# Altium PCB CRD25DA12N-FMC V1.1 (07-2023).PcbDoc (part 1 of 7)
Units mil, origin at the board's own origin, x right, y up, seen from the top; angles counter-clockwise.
Board outline 8000 x 8000 mil, 6 copper layers (Top Layer, Layer 2, Layer 3, Layer 4, Layer 5, Bottom Layer), stack 91 mil thick; 542 components, 315 nets, 1585 pads, 558 vias.
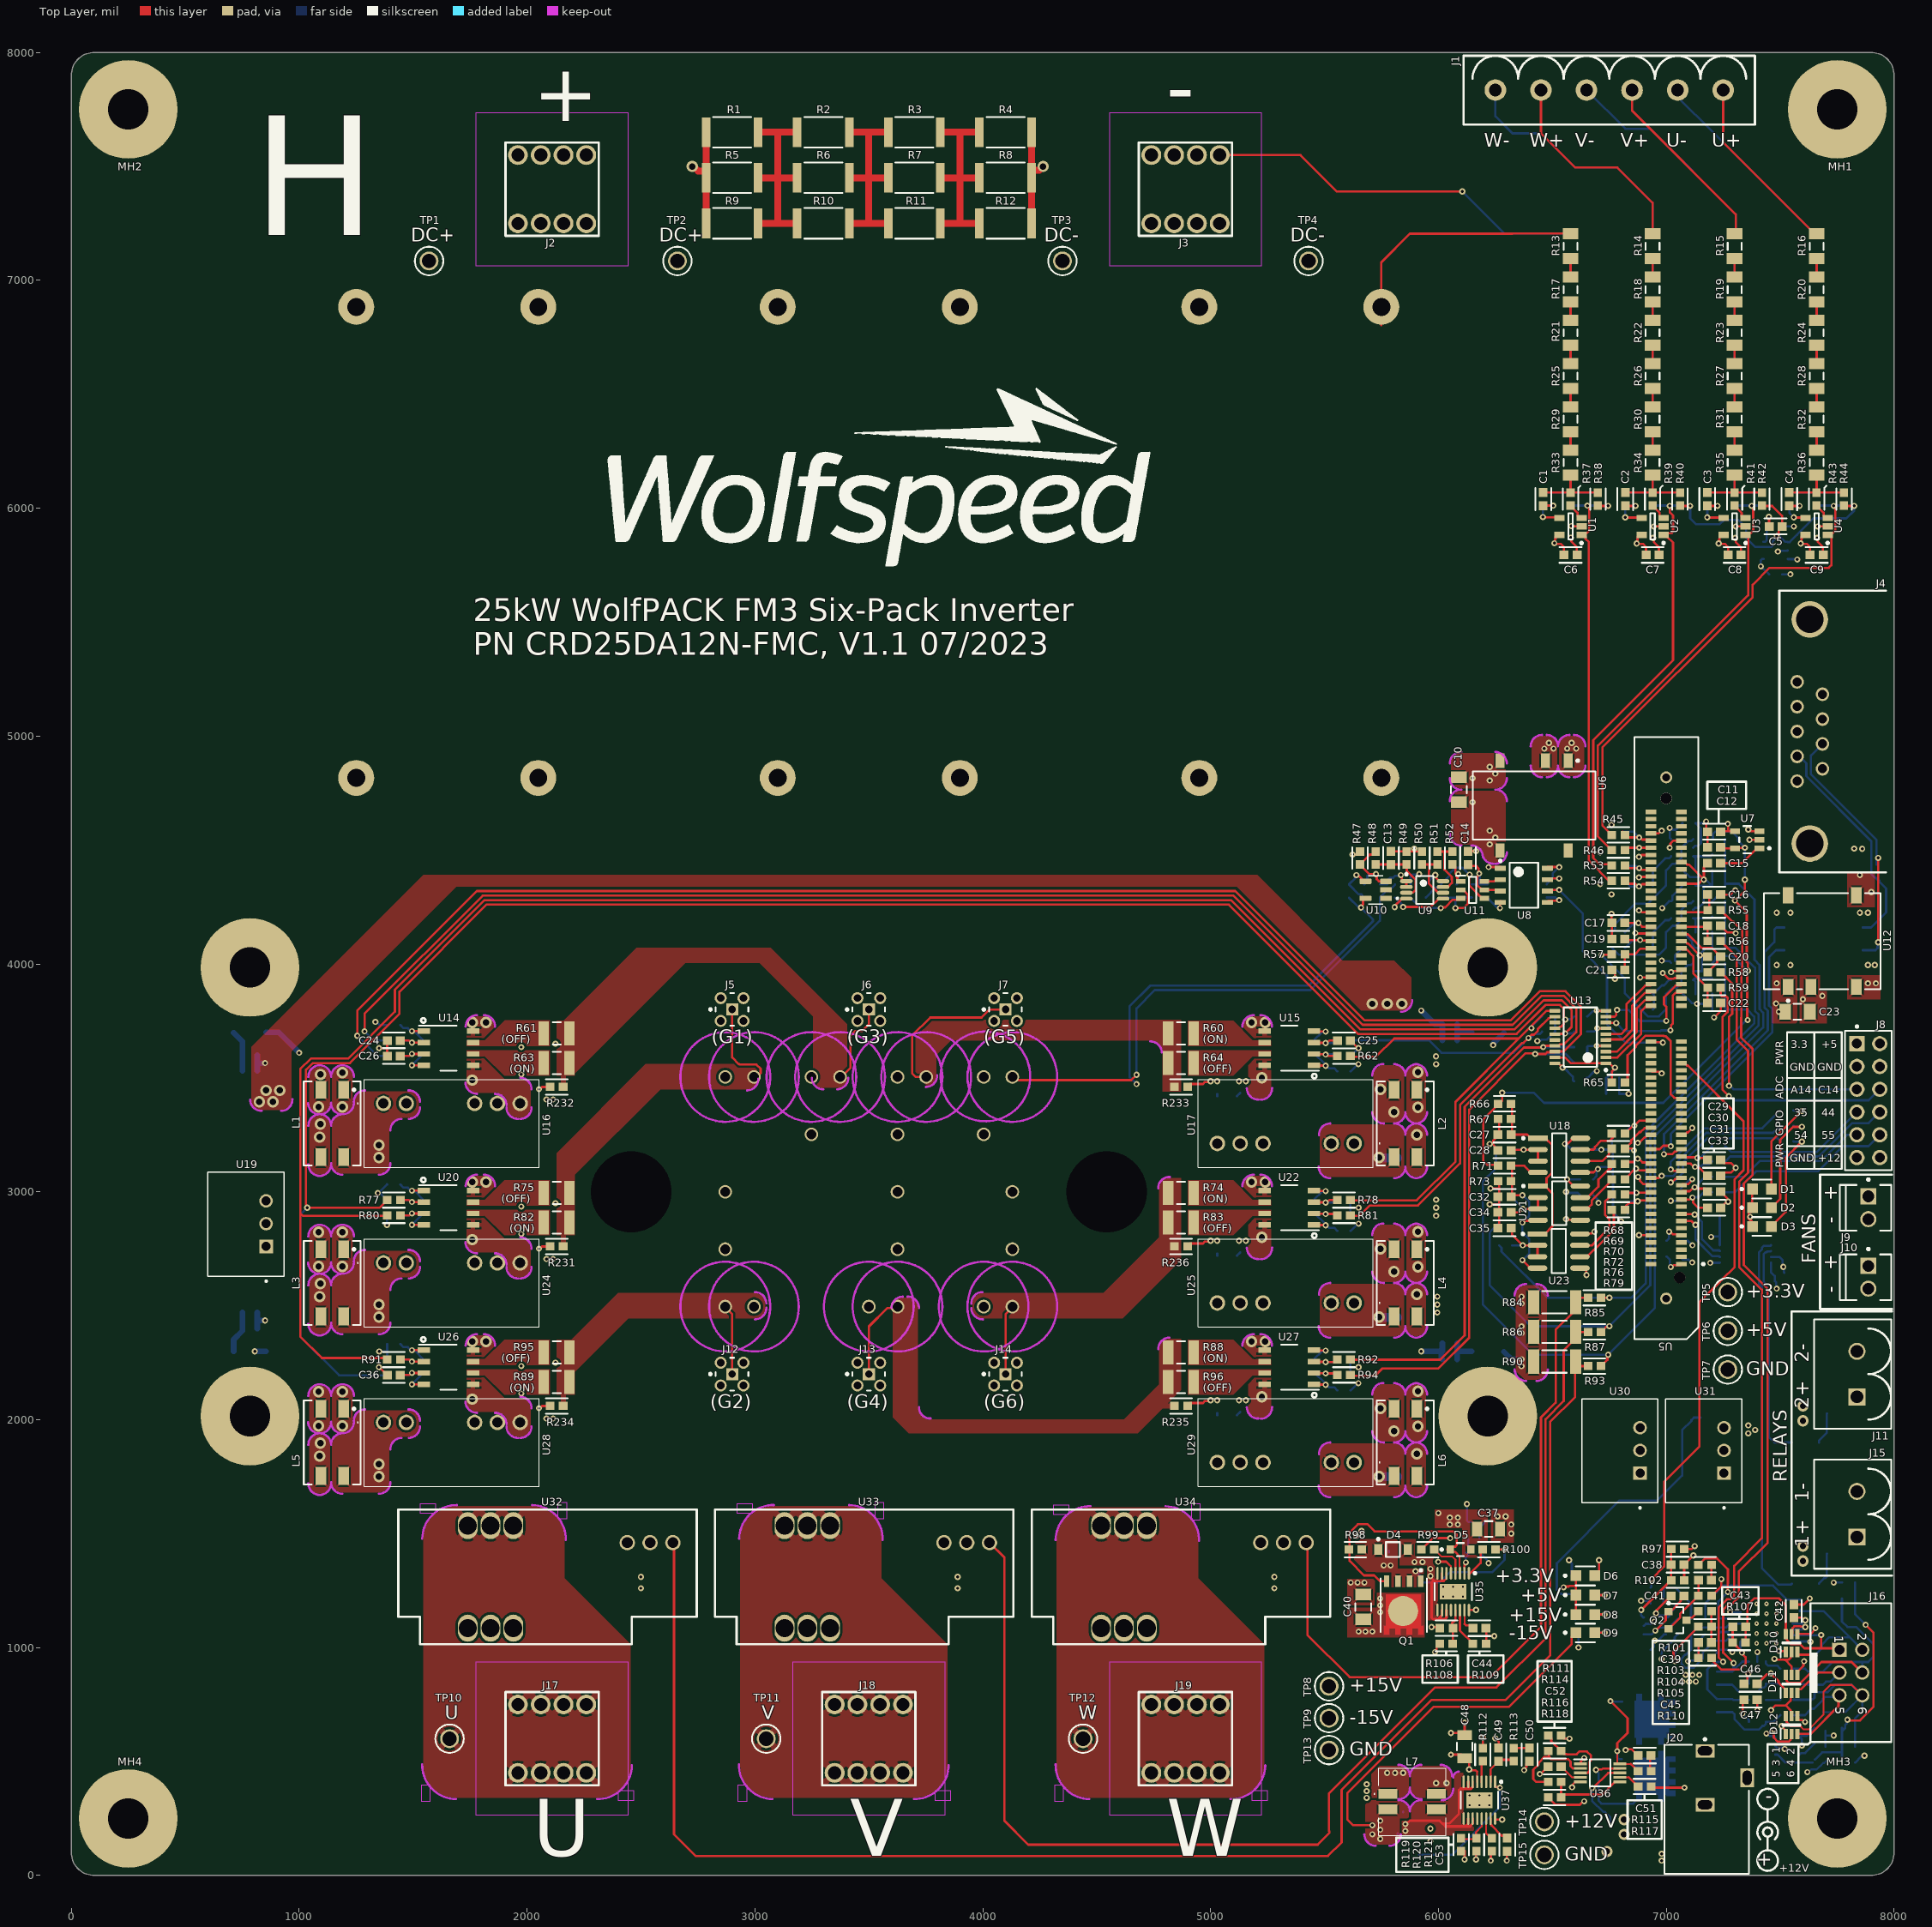
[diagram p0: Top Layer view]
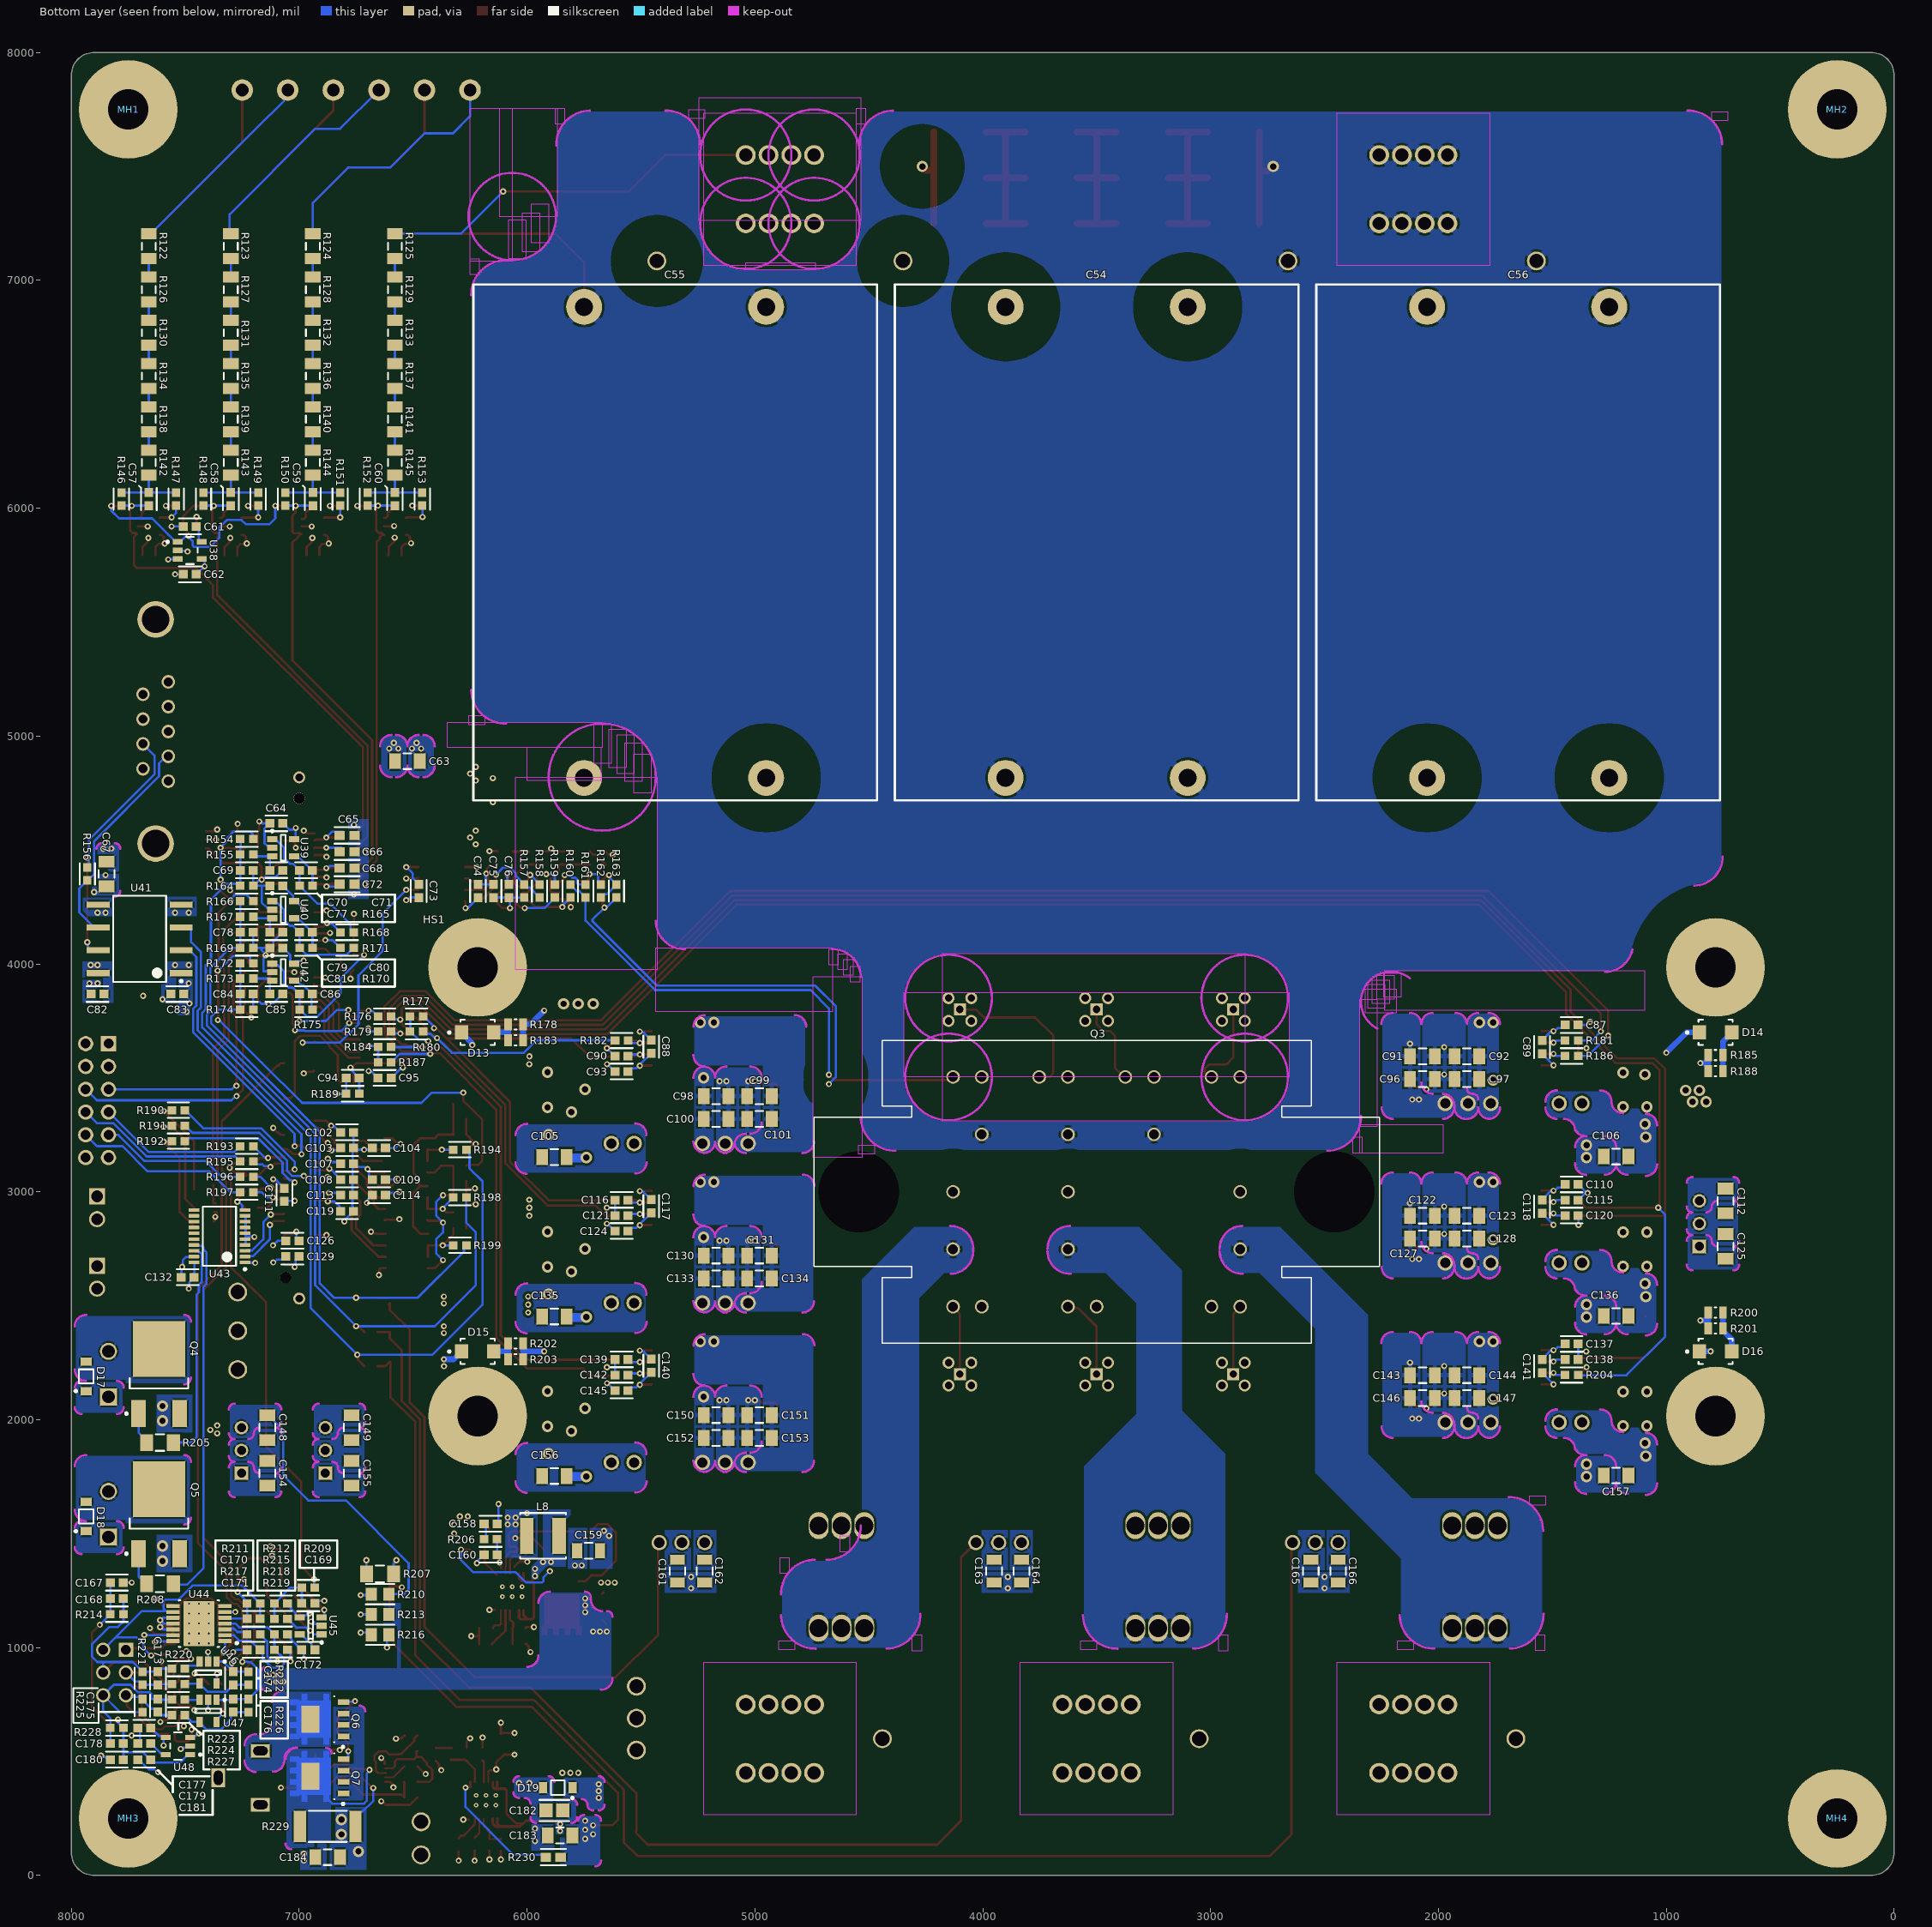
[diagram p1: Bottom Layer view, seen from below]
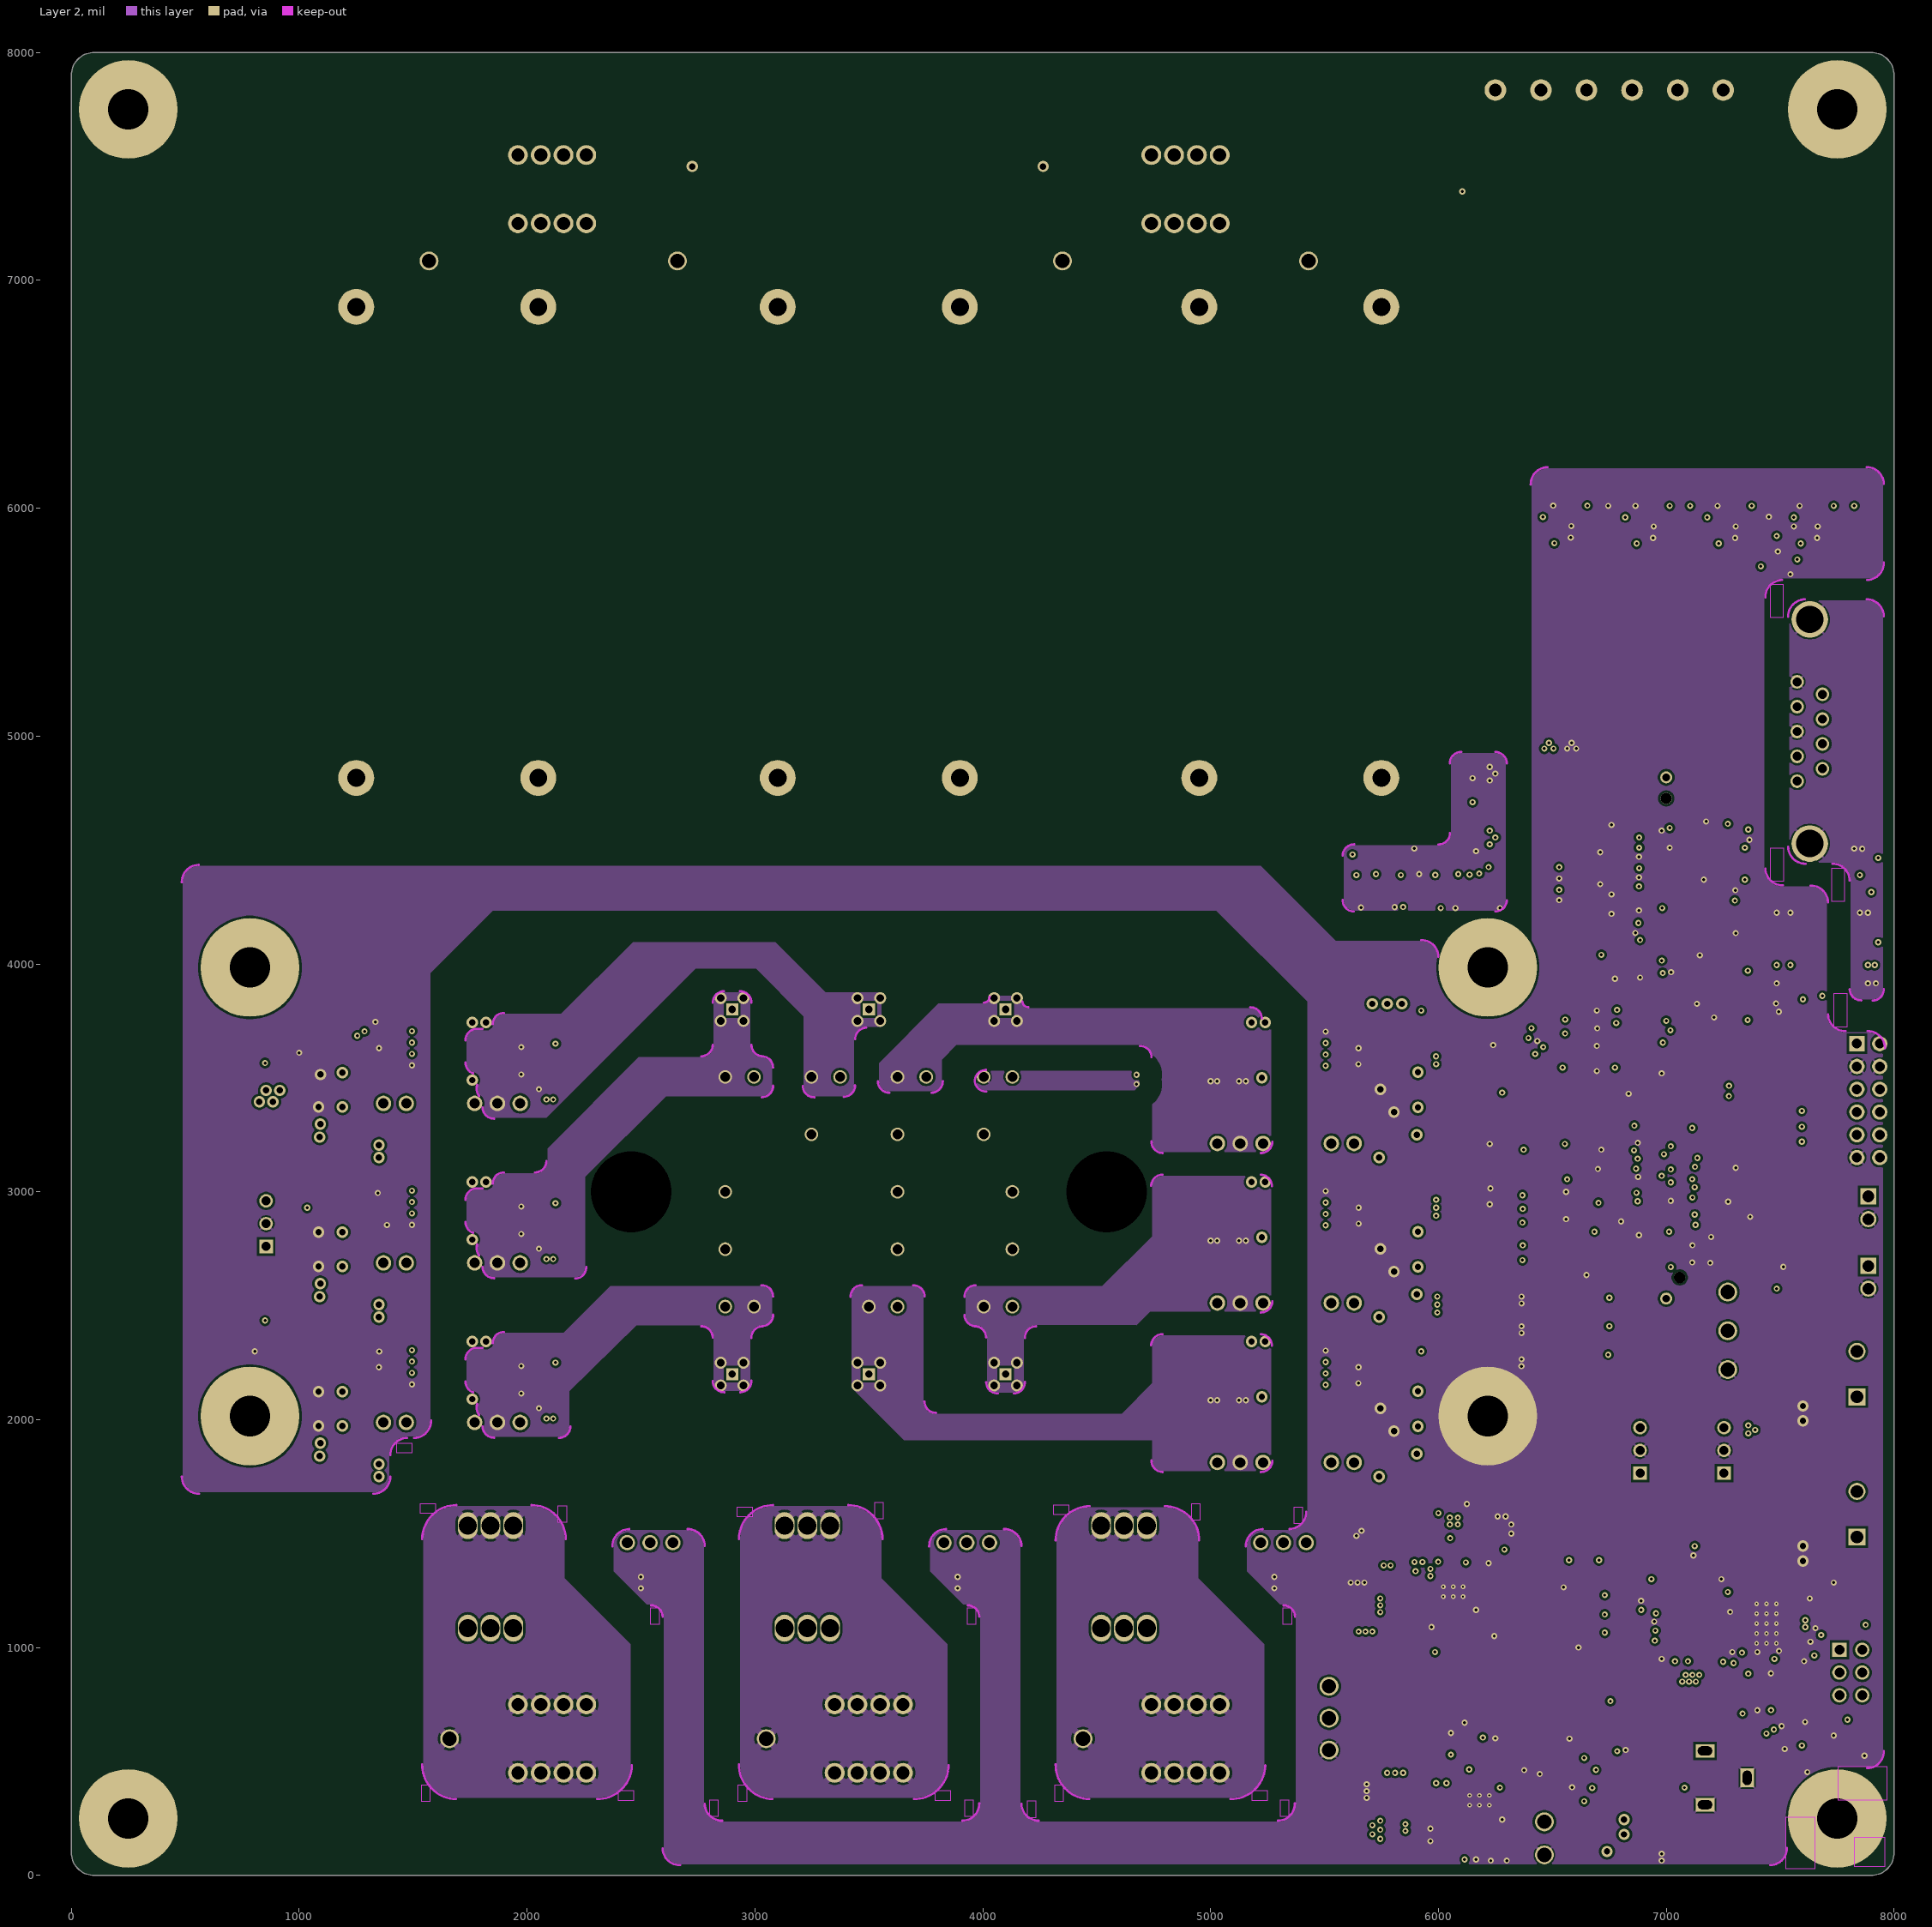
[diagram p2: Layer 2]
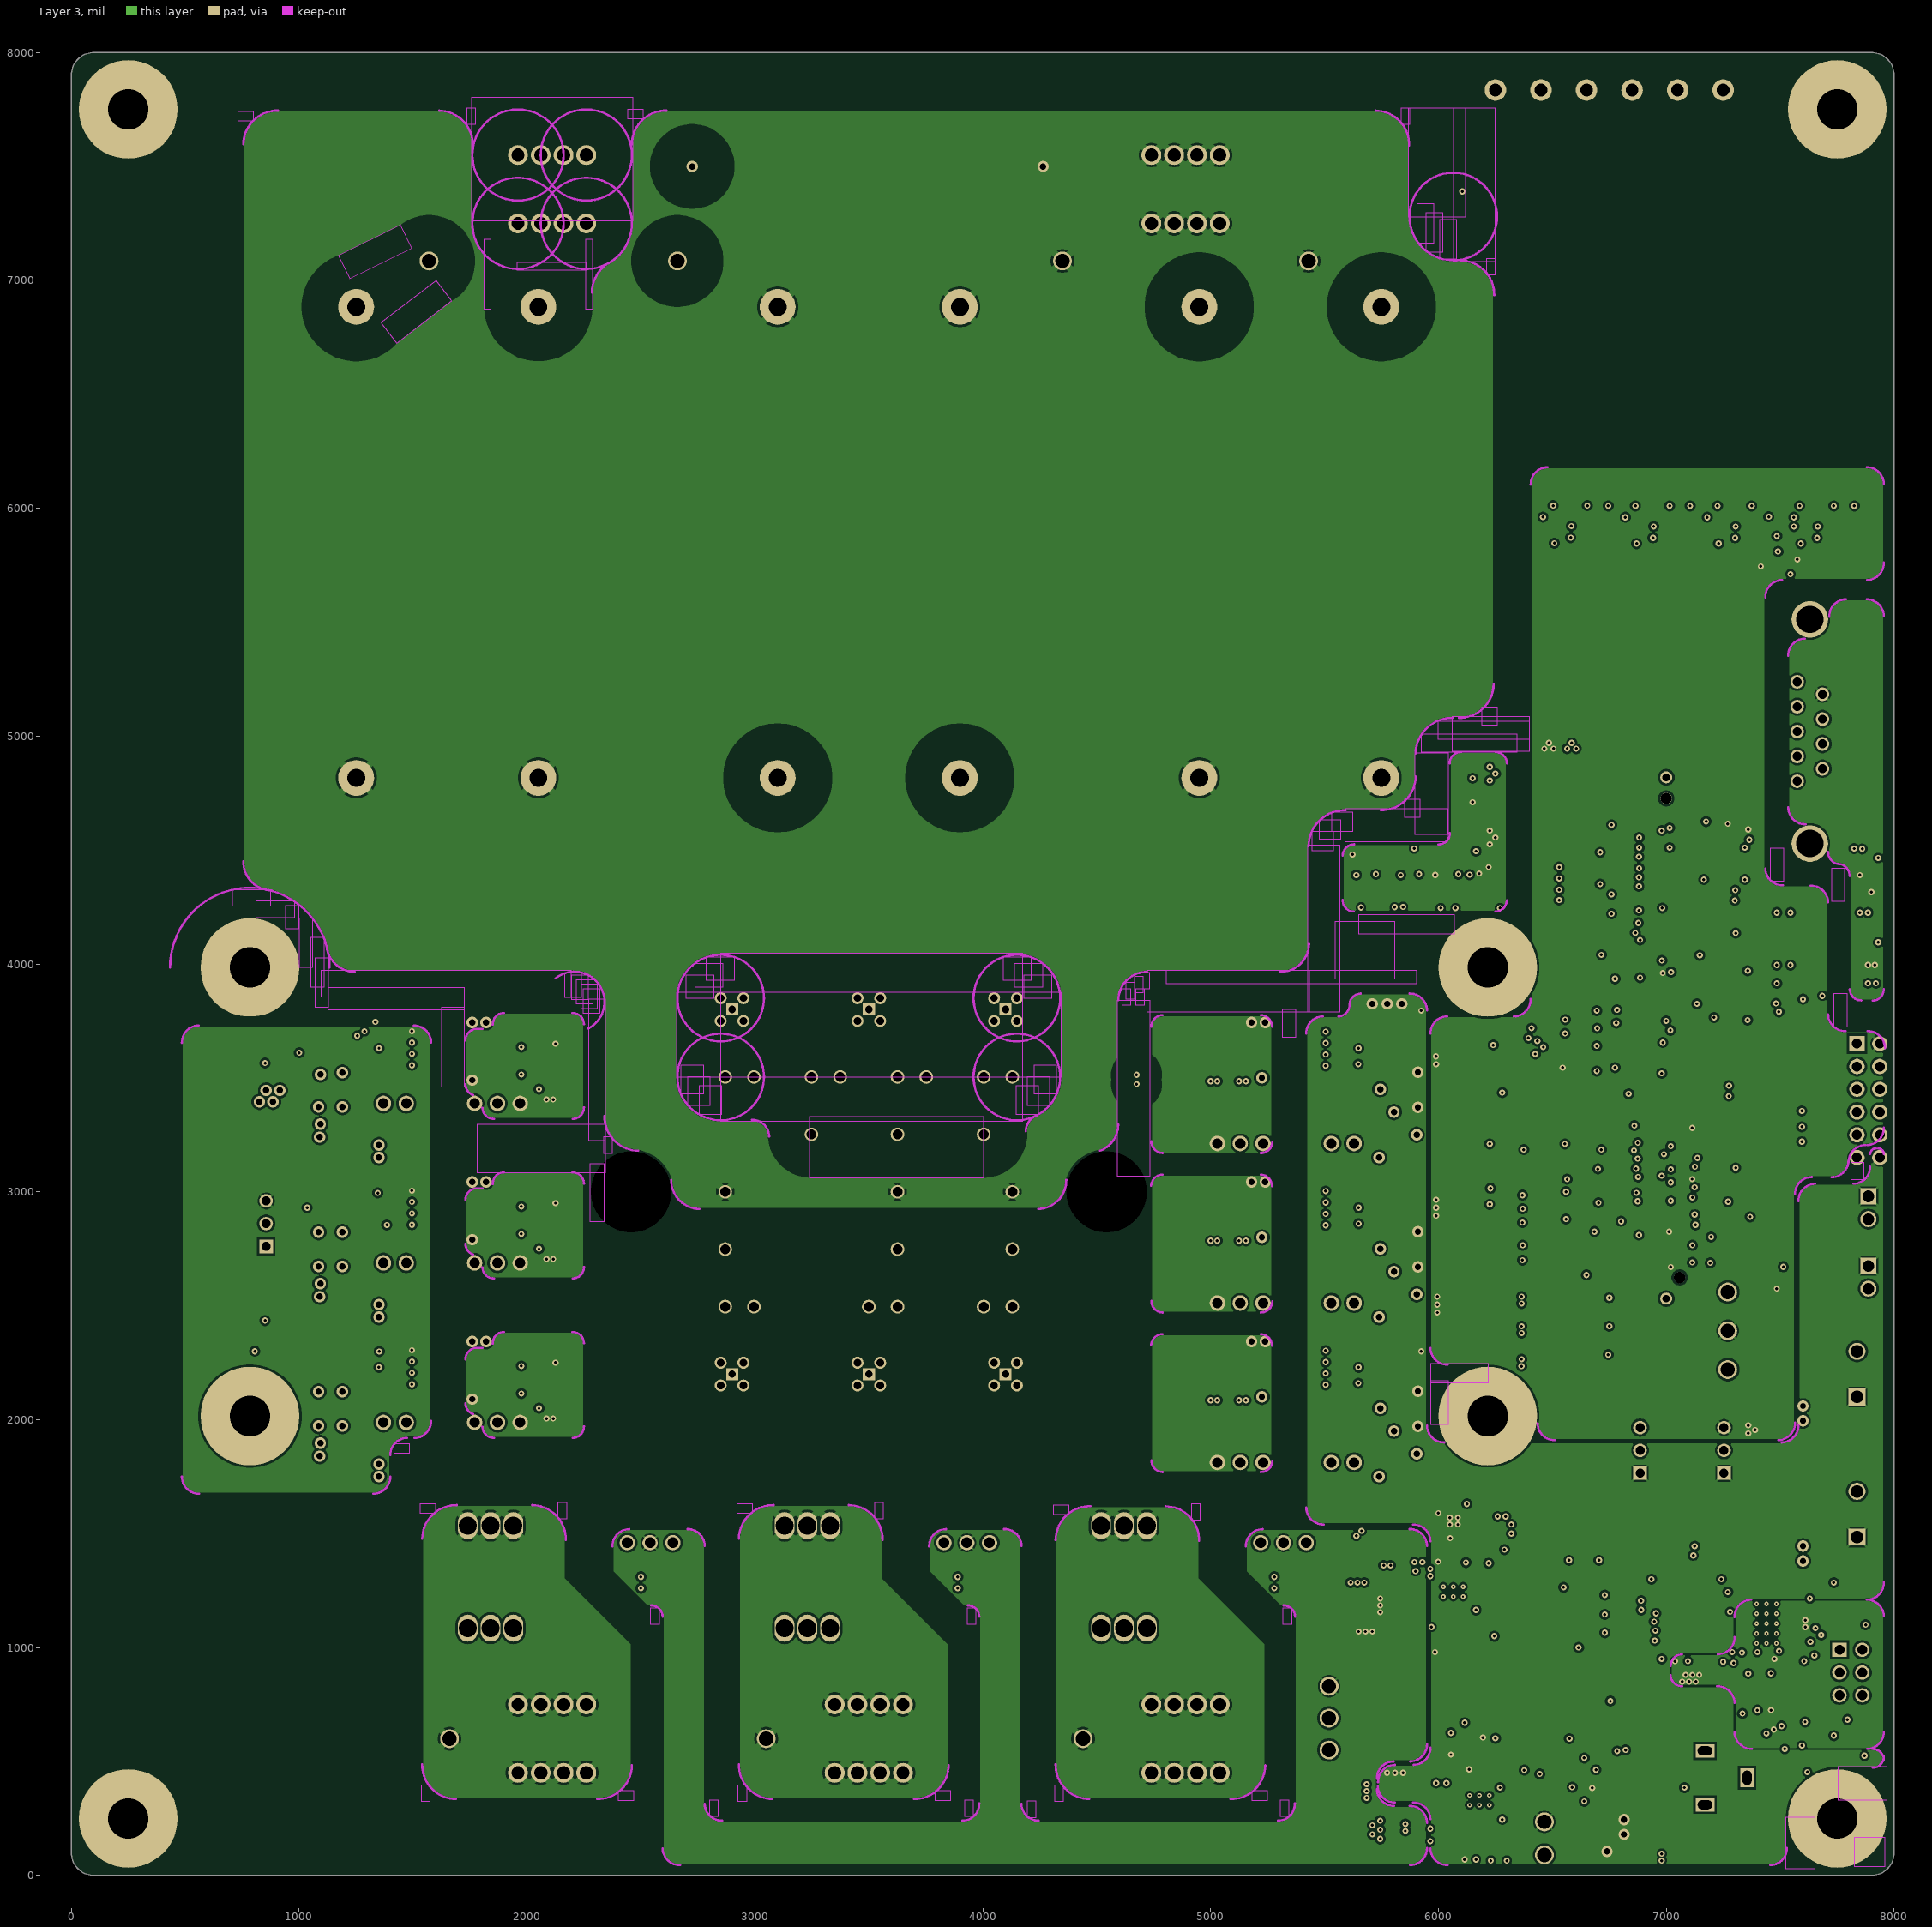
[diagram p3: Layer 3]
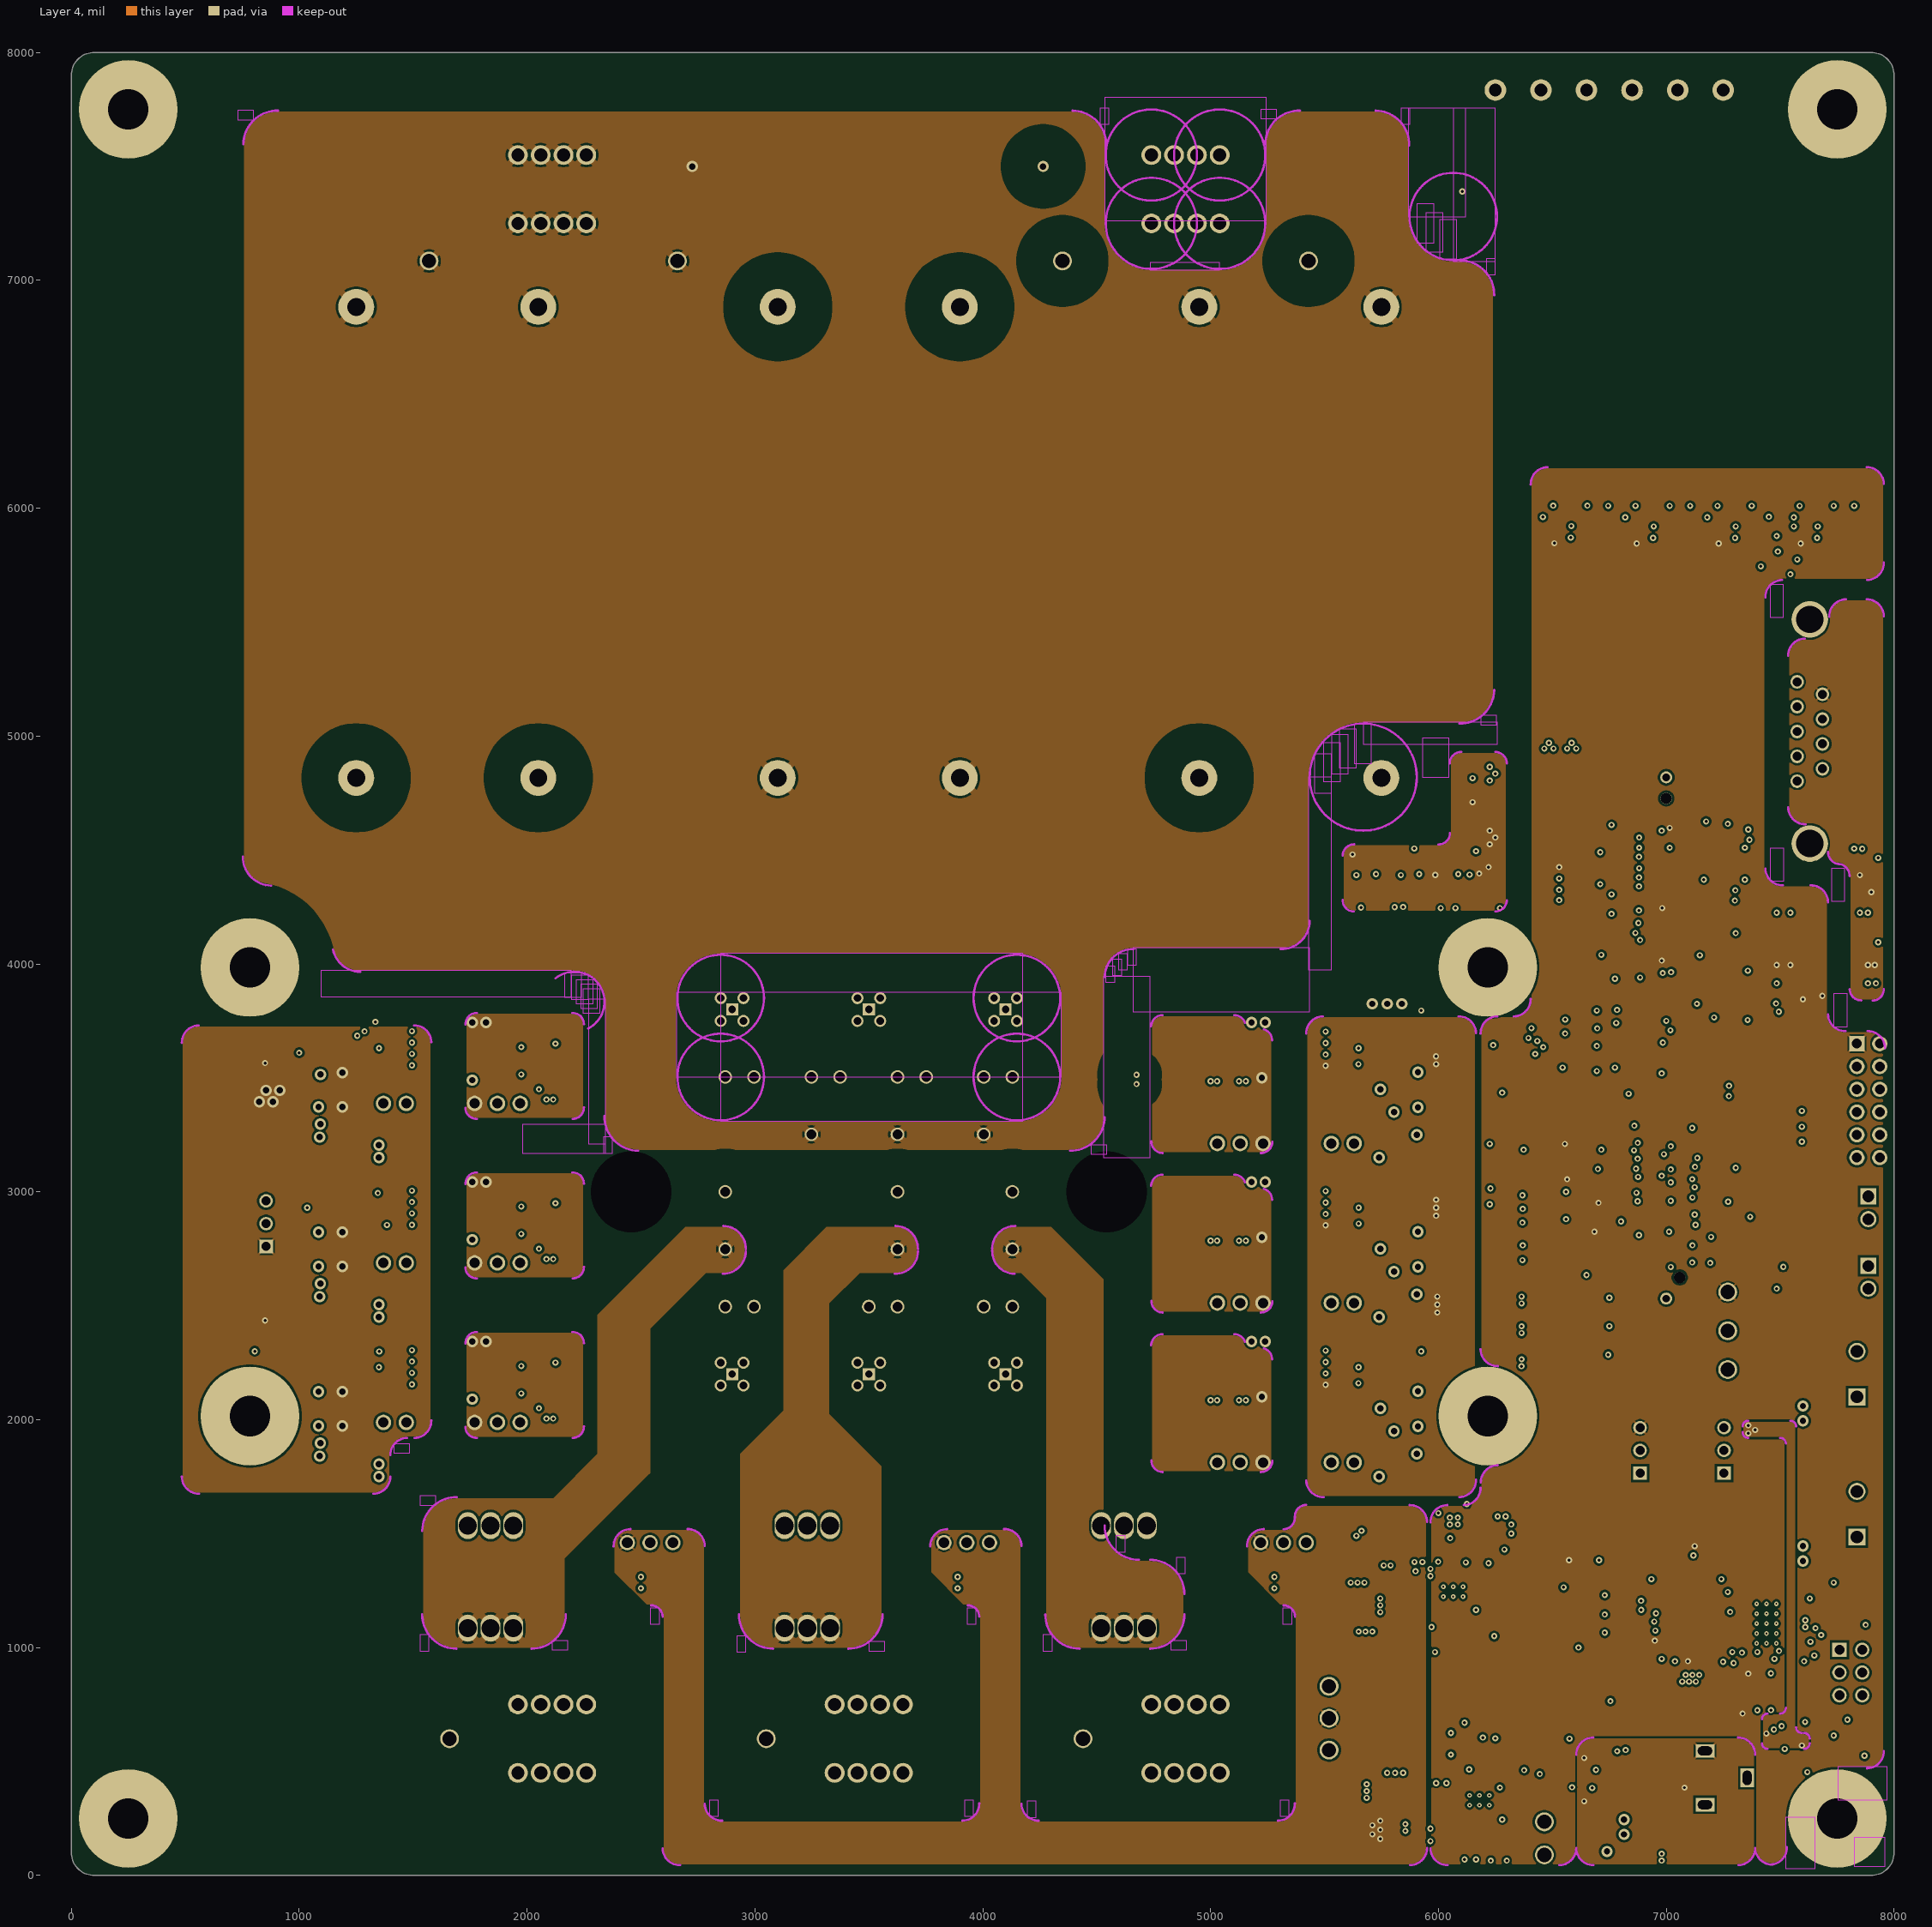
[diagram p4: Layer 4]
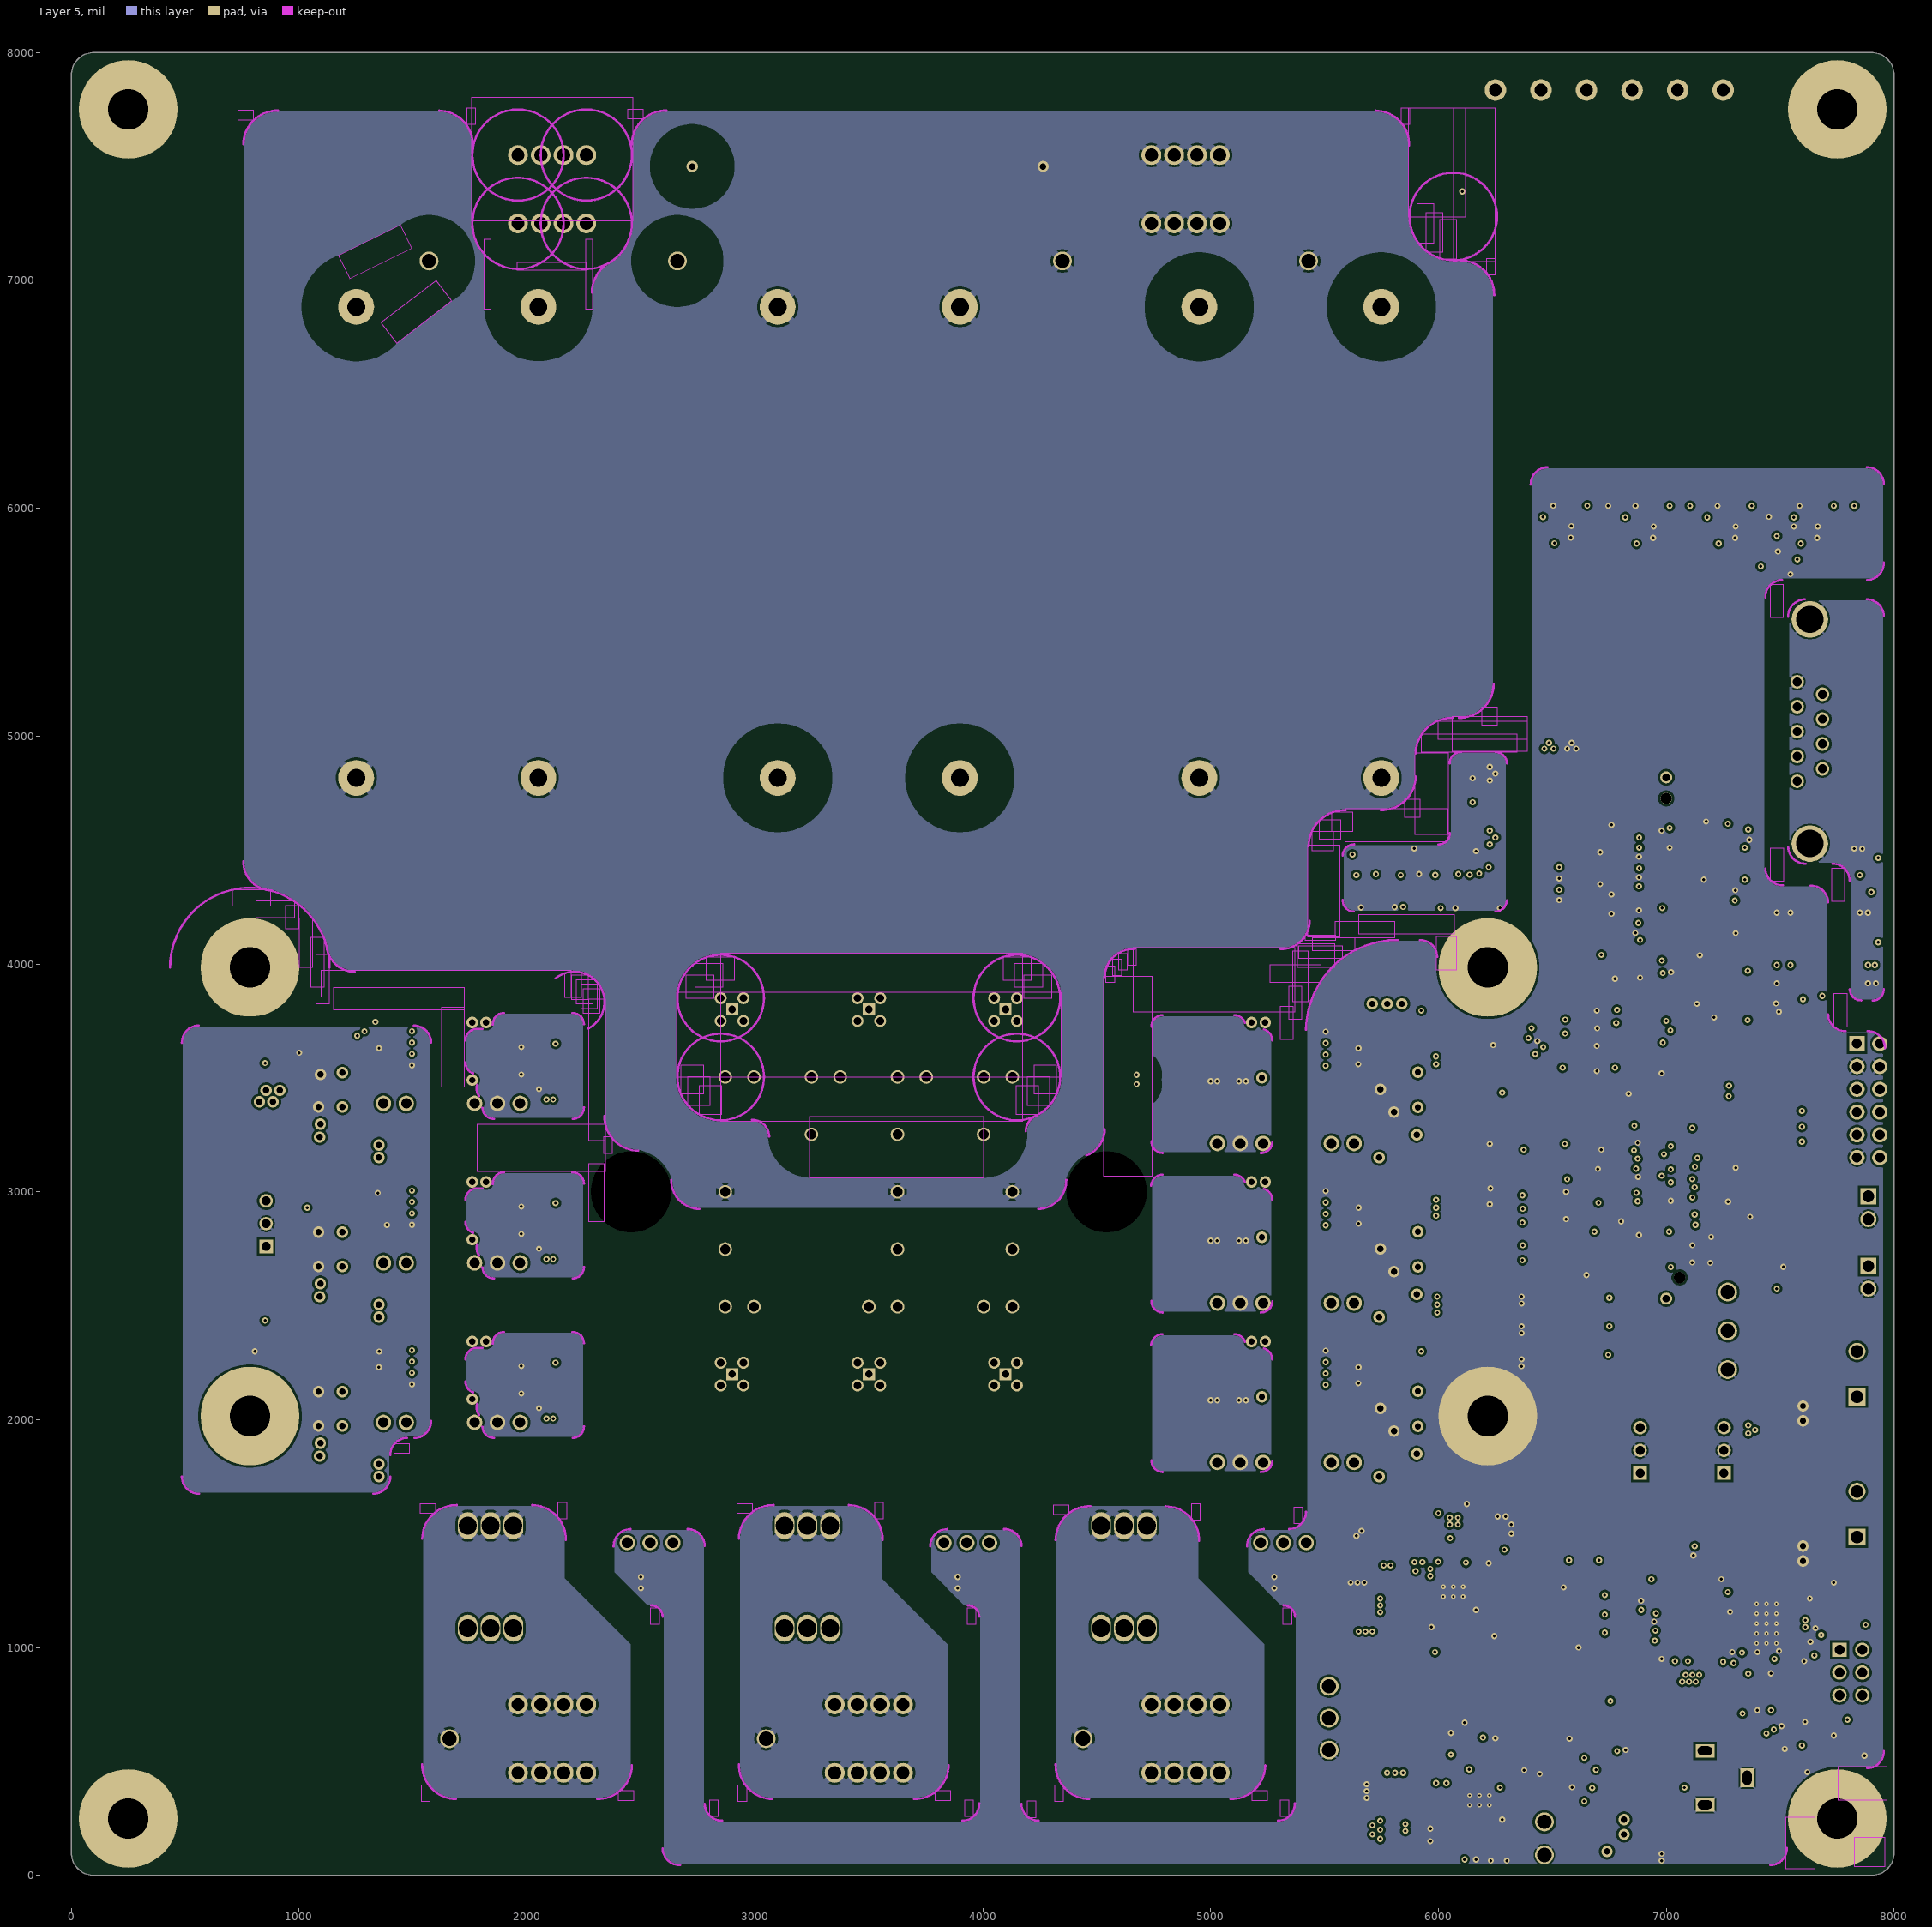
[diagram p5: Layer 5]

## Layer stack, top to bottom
Top Solder: solder mask 1, SM-002, Dk 4
Top Layer: signal copper 2.756
Dielectric 2: prepreg 7.894, PP-006, Dk 4.1
Layer 2: signal copper 2.756
Dielectric 4: prepreg 7.894, PP-006, Dk 4.1
Layer 3: signal copper 2.756
Dielectric 1: dielectric 42.888, FR-4, Dk 4.8
Layer 4: signal copper 2.756
Dielectric 5: prepreg 7.894, PP-006, Dk 4.1
Layer 5: signal copper 2.756
Dielectric 3: prepreg 7.894, PP-006, Dk 4.1
Bottom Layer: signal copper 2.756
Bottom Solder: solder mask 1, SM-002, Dk 4

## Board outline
0,100 0,7900 cw(c100,7900) 100,8000 7900,8000 cw(c7900,7900) 8000,7900 8000,100 cw(c7900,100) 7900,0 100,0 cw(c100,100)

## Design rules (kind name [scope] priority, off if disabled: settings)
Clearance Keepout [IsKeepOut] p1: gap=0 ignorepadtopadclearanceinfootprint=FALSE
Clearance DC+/- [InNet('DC+') vs InNet('DC-')] p2: gap=160 ignorepadtopadclearanceinfootprint=FALSE except(0: Arc-Text Arc-Hole Track-Text Track-Hole SMDPad-Text SMDPad-Hole THPad-Text THPad-Hole Via-Text Via-Hole Fill-Text Fill-Hole Poly-Text Poly-Hole Region-Text Region-Hole Text-Text Text-Hole)
Clearance DC+ [InNet('DC+') vs NOT (HoleDiameter > 180) AND NOT InNet('DC+1')] p3: gap=160 ignorepadtopadclearanceinfootprint=FALSE except(0: Arc-Text Arc-Hole Track-Text Track-Hole SMDPad-Text SMDPad-Hole THPad-Text THPad-Hole Via-Text Via-Hole Fill-Text Fill-Hole Poly-Text Poly-Hole Region-Text Region-Hole Text-Text Text-Hole)
Clearance +15V [InNet('+15V') vs InNet('+15V')] p4: gap=0 ignorepadtopadclearanceinfootprint=FALSE
Clearance VIN [InNet('VIN') vs InNet('VIN')] p5: gap=0 ignorepadtopadclearanceinfootprint=FALSE
Clearance VIN_PROTECT [InNet('VIN_PROTECT') vs InNet('VIN_PROTECT')] p6: gap=0 ignorepadtopadclearanceinfootprint=FALSE
Clearance U [InNetClass('U Class') vs NOT InNetClass('U Class') AND NOT (HoleDiameter > 100)] p7: gap=99 ignorepadtopadclearanceinfootprint=FALSE except(0: Arc-Text Arc-Hole Track-Text Track-Hole SMDPad-Text SMDPad-Hole THPad-Text THPad-Hole Via-Text Via-Hole Fill-Text Fill-Hole Poly-Text Poly-Hole Region-Text Region-Hole Text-Text Text-Hole)
Clearance V [InNetClass('V Class') vs NOT InNetClass('V Class') AND NOT IsKeepOut] p8: gap=99 ignorepadtopadclearanceinfootprint=FALSE except(0: Arc-Text Arc-Hole Track-Text Track-Hole SMDPad-Text SMDPad-Hole THPad-Text THPad-Hole Via-Text Via-Hole Fill-Text Fill-Hole Poly-Text Poly-Hole Region-Text Region-Hole Text-Text Text-Hole)
Clearance W [InNetClass('W Class') vs NOT InNetClass('W Class')] p9: gap=99 ignorepadtopadclearanceinfootprint=FALSE except(0: Arc-Text Arc-Hole Track-Text Track-Hole SMDPad-Text SMDPad-Hole THPad-Text THPad-Hole Via-Text Via-Hole Fill-Text Fill-Hole Poly-Text Poly-Hole Region-Text Region-Hole Text-Text Text-Hole)
Clearance DC- [InNetClass('DC- Class') vs NOT InNetClass('DC- Class') AND NOT InNet('DC-1') AND NOT (HoleDiameter > 180)] p10: gap=99 ignorepadtopadclearanceinfootprint=FALSE except(0: Arc-Text Arc-Hole Track-Text Track-Hole SMDPad-Text SMDPad-Hole THPad-Text THPad-Hole Via-Text Via-Hole Fill-Poly Fill-Text Fill-Hole Poly-Text Poly-Hole Region-Text Region-Hole Text-Text Text-Hole)
Clearance [All] p11: gap=10 ignorepadtopadclearanceinfootprint=FALSE except(0: Arc-Hole Track-Hole SMDPad-Hole THPad-Hole Via-Hole Fill-Poly Fill-Hole Poly-Hole Region-Hole Text-Hole; 6: Arc-SMDPad Track-SMDPad SMDPad-SMDPad THPad-THPad)
Height [All] p1: minheight=0 maxheight=4100 prefheight=500
HoleSize [All] p1: absolutevalues=TRUE maxlimit=400 minlimit=5 maxpercent=80.000 minpercent=20.000
MinimumSolderMaskSliver [All] p1: minsoldermaskwidth=1.5
PolygonConnect BoltConnect [HoleDiameter=177.165] p1: thpad.connectstyle=Direct thpad.reliefconductorwidth=10 thpad.reliefentries=4 thpad.polygonreliefangle="90 Angle" thpad.airgapwidth=10 smdpad.connectstyle=Relief smdpad.reliefconductorwidth=10 smdpad.reliefentries=4 smdpad.polygonreliefangle="90 Angle" smdpad.airgapwidth=10 via.connectstyle=Relief via.reliefconductorwidth=10 via.reliefentries=4 via.polygonreliefangle="90 Angle" via.airgapwidth=10
PolygonConnect PourOverThruConnect [InNetClass('Pour-Over Thru Clas')] p2: thpad.connectstyle=Direct thpad.reliefconductorwidth=10 thpad.reliefentries=4 thpad.polygonreliefangle="90 Angle" thpad.airgapwidth=10 smdpad.connectstyle=Relief smdpad.reliefconductorwidth=20 smdpad.reliefentries=4 smdpad.polygonreliefangle="90 Angle" smdpad.airgapwidth=8 via.connectstyle=Direct via.reliefconductorwidth=10 via.reliefentries=4 via.polygonreliefangle="90 Angle" via.airgapwidth=10
PolygonConnect PourOverConnect [InNetClass('Pour-Over Class')] p3: connectstyle=Direct reliefconductorwidth=10 reliefentries=4 polygonreliefangle="90 Angle" airgapwidth=10
PolygonConnect ViaConnect [IsVia] p4: connectstyle=Direct reliefconductorwidth=10 reliefentries=4 polygonreliefangle="90 Angle" airgapwidth=10
PolygonConnect HighCurrentConnect [InNetClass('High-Current Class')] p5: thpad.connectstyle=Relief thpad.reliefconductorwidth=30 thpad.reliefentries=4 thpad.polygonreliefangle="45 Angle" thpad.airgapwidth=10 smdpad.connectstyle=Relief smdpad.reliefconductorwidth=10 smdpad.reliefentries=4 smdpad.polygonreliefangle="45 Angle" smdpad.airgapwidth=10 via.connectstyle=Direct via.reliefconductorwidth=10 via.reliefentries=4 via.polygonreliefangle="90 Angle" via.airgapwidth=10
PolygonConnect [All] p6: connectstyle=Relief reliefconductorwidth=10 reliefentries=4 polygonreliefangle="45 Angle" airgapwidth=7
RoutingVias [All] p1: holewidth=28 width=50 viastyle="Through Hole" minholewidth=28 minwidth=50 maxholewidth=28 maxwidth=50
SilkToSilkClearance [All] p1: silktosilkclearance=4
SilkToSolderMaskClearance [IsPad] p1: minsilkscreentomaskgap=2 clearancetoexposedcopper=TRUE
SolderMaskExpansion [All] p1: expansion=4 istentingtop=FALSE
Width [All] p1: maxlimit=100 minlimit=6.5 preferedwidth=10 minimp=50.000000 maximp=50.000000 favimp=50.000000
25 further rules are at their usual default settings.

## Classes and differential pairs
net class "Pour-Over Thru Clas": +15V_U_HS +15V_U_LS +15V_V_HS +15V_V_LS +15V_W_HS +15V_W_LS -3V_U_HS -3V_U_LS -3V_V_HS -3V_V_LS -3V_W_HS -3V_W_LS S1 S2 S3 S4 S5 S6
net class "Pour-Over Class": G1 G1H G1L G2 G2H G2L G3 G3H G3L G4 G4H G4L G5 G5H G5L G6 G6H G6L
net class "High-Current Class": DC+ DC- U U_OUT V V_OUT W W_OUT
net class "Bleed Class": BLEED1 BLEED2 BLEED3
net class "DC- Class": +15V_U_LS +15V_V_LS +15V_W_LS -3V_U_LS -3V_V_LS -3V_W_LS DC- G2 G2H G2L G4 G4H G4L G6 G6H G6L S2 S4 S6
net class "W Class": +15V_W_HS -3V_W_HS G5 G5H G5L S5 W W_OUT
net class "V Class": +15V_V_HS -3V_V_HS G3 G3H G3L S3 V V_OUT
net class "U Class": +15V_U_HS -3V_U_HS G1 G1H G1L S1 U U_OUT
component class "08 - Resolver": C16 C18 C38 C39 C41 C42 C43 C45 C46 C47 C167 C168 C169 C170 C171 C172 C173 C174 C175 C176 C178 C180 D10 D11 D12 J16 Q2 R55 R56 R97 R101 R102 R103 R104 R105 R107 R110 R209 R211 R212 R214 R215 R217 R218 R219 R220 R221 R222 R223 R224 R225 R226 R227 R228 U44 U45 U46 U47
component class "02 - Power Stage": C54 C55 C56 C161 C162 C163 C164 C165 C166 D13 D14 D15 D16 HS1 J2 J3 J5 J6 J7 J12 J13 J14 J17 J18 J19 MH1 MH2 MH3 MH4 Q3 R1 R2 R3 R4 R5 R6 R7 R8 R9 R10 R11 R12 R178 R183 R185 R188 R200 R201 R202 R203 TP1 TP2 TP3 TP4 TP10 TP11 TP12 U32 U33 U34
component class "04 - Auxiliary Power": C5 C10 C11 C12 C15 C23 C37 C40 C44 C48 C49 C50 C51 C52 C53 C61 C62 C63 C67 C112 C125 C148 C149 C154 C155 C158 C159 C160 C177 C179 C181 C182 C183 C184 D4 D5 D6 D7 D8 D9 D19 J9 J10 J20 L7 L8 Q1 Q6 Q7 R98 R99 R100 R106 R108 R109 R111 R112 R113 R114 R115 R116 R117 R118 R119 R120 R121 R206 R207 R210 R213 R216 R229 R230 TP5 TP6 TP7 TP8 TP9 TP13 TP14 TP15 U6 U7 U12 U19 U30 U31 U35 U36 U37 U38 U48
component class "07 - Current Sense": C17 C19 C21 C27 C28 C32 C34 C35 C64 C69 C70 C71 C77 C78 C79 C80 C81 C84 C85 C86 C102 C103 C104 C107 C108 C109 C113 C114 C119 R57 R66 R67 R68 R69 R70 R71 R72 R73 R76 R79 R84 R85 R86 R87 R90 R93 R154 R155 R164 R165 R166 R167 R168 R169 R170 R171 R172 R173 R174 R175 R194 R198 R199 U18 U21 U23 U39 U40 U42
component class "03 - Controller": C20 C22 C29 C30 C31 C33 C82 C83 C111 C126 C129 C132 D1 D2 D3 D17 D18 J4 J8 J11 J15 Q4 Q5 R58 R59 R156 R190 R191 R192 R193 R195 R196 R197 R205 R208 U5 U41 U43
component class "06 - Voltage Sense": C1 C2 C3 C4 C6 C7 C8 C9 C57 C58 C59 C60 C65 C66 C68 C72 J1 R13 R14 R15 R16 R17 R18 R19 R20 R21 R22 R23 R24 R25 R26 R27 R28 R29 R30 R31 R32 R33 R34 R35 R36 R37 R38 R39 R40 R41 R42 R43 R44 R45 R46 R53 R54 R122 R123 R124 R125 R126 R127 R128 R129 R130 R131 R132 R133 R134 R135 R136 R137 R138 R139 R140 R141 R142 R143 R144 R145 R146 R147 R148 R149 R150 R151 R152 R153 U1 U2 U3 U4
component class "05 - Gate Drivers": C13 C14 C24 C25 C26 C36 C73 C74 C75 C76 C87 C88 C89 C90 C91 C92 C93 C94 C95 C96 C97 C98 C99 C100 C101 C105 C106 C110 C115 C116 C117 C118 C120 C121 C122 C123 C124 C127 C128 C130 C131 C133 C134 C135 C136 C137 C138 C139 C140 C141 C142 C143 C144 C145 C146 C147 C150 C151 C152 C153 C156 C157 L1 L2 L3 L4 L5 L6 R47 R48 R49 R50 R51 R52 R60 R61 R62 R63 R64 R65 R74 R75 R77 R78 R80 R81 R82 R83 R88 R89 R91 R92 R94 R96 R157 R158 R159 R160 R161 R162 R163 R176 R177 R179 R180 R181 R182 R184 R186 R187 R189 R204 R231 R232 R233 R234 R235 R236 U8 U9 U10 U11 U13 U14 U15 U16 U17 U20 U22 U24 U25 U26 U27 U28 U29

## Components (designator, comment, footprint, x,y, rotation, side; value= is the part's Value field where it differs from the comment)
C1 "C0603C472K3RAC7867" FP-C0603C-CF-IPC_B 6460,6040 r270 top value=4.7nF
C2 "CL10B103KA8WPNC" FP-C0603C-CF-IPC_B 6820,6040 r270 top value=10nF
C3 "CL10B103KA8WPNC" FP-C0603C-CF-IPC_B 7180,6040 r270 top value=10nF
C4 "CL10B103KA8WPNC" FP-C0603C-CF-IPC_B 7540,6040 r270 top value=10nF
C5 "C0603C104K3RACTU" FP-C0603C-CF-IPC_B 7480,5920 r180 top value=0.10μF
C6 "C0603C104K3RACTU" FP-C0603C-CF-IPC_B 6580,5795 r0 top value=0.10μF
C7 "C0603C104K3RACTU" FP-C0603C-CF-IPC_B 6940,5795 r0 top value=0.10μF
C8 "C0603C104K3RACTU" FP-C0603C-CF-IPC_B 7300,5795 r0 top value=0.10μF
C9 "C0603C104K3RACTU" FP-C0603C-CF-IPC_B 7660,5795 r0 top value=0.10μF
C10 "CL31B106KAHSFNE" FP-CL31-IPC_B 6090,4765 r90 top value=10μF
C11 "C0603C104K3RACTU" FP-C0603C-CF-IPC_B 7210,4580 r180 top value=0.10μF
C12 "C0603C104K3RACTU" FP-C0603C-CF-IPC_B 7210,4511 r180 top value=0.10μF
C13 "C0603C104K3RACTU" FP-C0603C-CF-IPC_B 5792,4465 r90 top value=0.10μF
C14 "C0603C104K3RACTU" FP-C0603C-CF-IPC_B 6130,4465 r90 top value=0.10μF
C15 "C0603C104K3RACTU" FP-C0603C-CF-IPC_B 7210,4442 r180 top value=0.10μF
C16 "C0603C102K5RACAUTO" FP-C0603C-CF-IPC_B 7210,4304 r0 top value=1nF
C17 "C0603C472K3RAC7867" FP-C0603C-CF-IPC_B 6790,4180 r180 top value=4.7nF
C18 "C0603C102K5RACAUTO" FP-C0603C-CF-IPC_B 7210,4168 r0 top value=1nF
C19 "C0603C472K3RAC7867" FP-C0603C-CF-IPC_B 6790,4110 r180 top value=4.7nF
C20 "CL10C560JB8NNNC" FP-C0603C-CF-IPC_B 7210,4032 r180 top value=56pF
C21 "C0603C472K3RAC7867" FP-C0603C-CF-IPC_B 6790,3974 r180 top value=4.7nF
C22 "CL10C560JB8NNNC" FP-C0603C-CF-IPC_B 7210,3828 r0 top value=56pF
C23 "CL31B106KAHSFNE" FP-CL31-IPC_B 7575.81,3790 r180 top value=10μF
C24 "CL10C560JB8NNNC" FP-C0603C-CF-IPC_B 1415,3664 r180 top value=56pF
C25 "CL10C560JB8NNNC" FP-C0603C-CF-IPC_B 5585,3664 r0 top value=56pF
C26 "CL10C560JB8NNNC" FP-C0603C-CF-IPC_B 1415,3596 r180 top value=56pF
C27 "C0603C104K3RACTU" FP-C0603C-CF-IPC_B 6290,3251 r180 top value=0.10μF
C28 "C0603C472K3RAC7867" FP-C0603C-CF-IPC_B 6290,3182 r180 top value=4.7nF
C29 "CL10C560JB8NNNC" FP-C0603C-CF-IPC_B 7210,3140 r0 top value=56pF
C30 "CL10C560JB8NNNC" FP-C0603C-CF-IPC_B 7210,3070 r0 top value=56pF
C31 "CL10C560JB8NNNC" FP-C0603C-CF-IPC_B 7210,3000 r0 top value=56pF
C32 "C0603C104K3RACTU" FP-C0603C-CF-IPC_B 6290,2978 r180 top value=0.10μF
C33 "CL10C560JB8NNNC" FP-C0603C-CF-IPC_B 7210,2930 r0 top value=56pF
C34 "C0603C472K3RAC7867" FP-C0603C-CF-IPC_B 6290,2910 r180 top value=4.7nF
C35 "C0603C472K3RAC7867" FP-C0603C-CF-IPC_B 6290,2840 r180 top value=4.7nF
C36 "CL10C560JB8NNNC" FP-C0603C-CF-IPC_B 1415,2196 r180 top value=56pF
C37 "CL31B475KBHNFNE" FP-CL31-IPC_C 6220,1520 r0 top value=4.7μF
C38 "C0603C104K3RACTU" FP-C0603C-CF-IPC_B 7050,1363 r0 top value=0.10μF
C39 "CL10B103KA8WPNC" FP-C0603C-CF-IPC_B 7170,1295 r180 top value=10nF
C40 "CL31B106KAHSFNE" FP-CL31-IPC_B 5670,1178.12 r90 top value=10μF
C41 "C0603C102K5RACAUTO" FP-C0603C-CF-IPC_B 7050,1227 r180 top value=1nF
C42 "C0603C104K3RACTU" FP-C0603C-CF-IPC_B 7560,1160 r90 top value=0.10μF
C43 "06035A180JAT2A" FP-C0603C-CF-IPC_B 7320,1091 r0 top value=18pF
C44 "C0603C104K3RACTU" FP-C0603C-CF-IPC_B 6180,1085 r0 top value=0.10μF
C45 "CL10B103KA8WPNC" FP-C0603C-CF-IPC_B 7170,1022 r0 top value=10nF
C46 "C0603C104K3RACTU" FP-C0603C-CF-IPC_B 7370,840 r0 top value=0.10μF
C47 "C0603C104K3RACTU" FP-C0603C-CF-IPC_B 7370,771 r0 top value=0.10μF
C48 "CL31B475KBHNFNE" FP-CL31-IPC_C 6115,565 r90 top value=4.7μF
C49 "CL10C560JB8NNNC" FP-C0603C-CF-IPC_B 6263,530 r90 top value=56pF
C50 "C0603C102K5RACAUTO" FP-C0603C-CF-IPC_B 6400,530 r270 top value=1nF
C51 "C0603C472K3RAC7867" FP-C0603C-CF-IPC_B 6905,526 r180 top value=4.7nF
C52 "CC0805KRX7R9BB223" FP-C0603C-CF-IPC_B 6510,478 r180 top value=22nF
C53 "C0603C104K3RACTU" FP-C0603C-CF-IPC_B 6302,135 r270 top value=0.10μF
C54 "C4AQQEW5650A3BJ" C4AQQEW5650A3BJ 3500,5850 r90 bottom value=65µF
C55 "C4AQQEW5650A3BJ" C4AQQEW5650A3BJ 5350,5850 r270 bottom value=65µF
C56 "C4AQQEW5650A3BJ" C4AQQEW5650A3BJ 1650,5850 r270 bottom value=65µF
C57 "CL10B103KA8WPNC" FP-C0603C-CF-IPC_B 7660,6040 r270 bottom value=10nF
C58 "CL10B103KA8WPNC" FP-C0603C-CF-IPC_B 7300,6040 r270 bottom value=10nF
C59 "CL10B103KA8WPNC" FP-C0603C-CF-IPC_B 6940,6040 r270 bottom value=10nF
C60 "C0603C472K3RAC7867" FP-C0603C-CF-IPC_B 6580,6040 r270 bottom value=4.7nF
C61 "C0603C104K3RACTU" FP-C0603C-CF-IPC_B 7480,5920 r0 bottom value=0.10μF
C62 "C0603C104K3RACTU" FP-C0603C-CF-IPC_B 7480,5710 r0 bottom value=0.10μF
C63 "CL31B106KAHSFNE" FP-CL31-IPC_B 6525,4890 r0 bottom value=10μF
C64 "C0603C104K3RACTU" FP-C0603C-CF-IPC_B 7100,4617 r0 bottom value=0.10μF
C65 "GCM188R71C274KA37D" FP-GCM188-0_1-IPC_A 6790,4564 r180 bottom value=0.27μF
C66 "GCM188R71C274KA37D" FP-GCM188-0_1-IPC_A 6790,4492 r180 bottom value=0.27μF
C67 "CL31B106KAHSFNE" FP-CL31-IPC_B 7845,4395 r90 bottom value=10μF
C68 "GCM188R71C274KA37D" FP-GCM188-0_1-IPC_A 6790,4420 r180 bottom value=0.27μF
C69 "C0603C472K3RAC7867" FP-C0603C-CF-IPC_B 7230,4411 r180 bottom value=4.7nF
C70 "CL10C101JB8NNNC" FP-C0603C-CF-IPC_B 7100,4411 r180 bottom value=100pF
C71 "CL10C101JB8NNNC" FP-C0603C-CF-IPC_B 6970,4411 r0 bottom value=100pF
C72 "GCM188R71C274KA37D" FP-GCM188-0_1-IPC_A 6790,4350 r180 bottom value=0.27μF
C73 "C0603C104K3RACTU" FP-C0603C-CF-IPC_B 6475,4320 r270 bottom value=0.10μF
C74 "C0603C104K3RACTU" FP-C0603C-CF-IPC_B 6215,4320 r270 bottom value=0.10μF
C75 "C0603C104K3RACTU" FP-C0603C-CF-IPC_B 6147,4320 r270 bottom value=0.10μF
C76 "C0603C104K3RACTU" FP-C0603C-CF-IPC_B 6079,4320 r270 bottom value=0.10μF
C77 "C0603C104K3RACTU" FP-C0603C-CF-IPC_B 7100,4343 r0 bottom value=0.10μF
C78 "C0603C472K3RAC7867" FP-C0603C-CF-IPC_B 7230,4139 r180 bottom value=4.7nF
C79 "CL10C101JB8NNNC" FP-C0603C-CF-IPC_B 7100,4139 r180 bottom value=100pF
C80 "CL10C101JB8NNNC" FP-C0603C-CF-IPC_B 6970,4139 r0 bottom value=100pF
C81 "C0603C104K3RACTU" FP-C0603C-CF-IPC_B 7100,4070 r0 bottom value=0.10μF
C82 "C0603C104K3RACTU" FP-C0603C-CF-IPC_B 7885,3868 r0 bottom value=0.10μF
C83 "C0603C104K3RACTU" FP-C0603C-CF-IPC_B 7535,3868 r180 bottom value=0.10μF
C84 "C0603C472K3RAC7867" FP-C0603C-CF-IPC_B 7230,3868 r180 bottom value=4.7nF
C85 "CL10C101JB8NNNC" FP-C0603C-CF-IPC_B 7100,3868 r180 bottom value=100pF
C86 "CL10C101JB8NNNC" FP-C0603C-CF-IPC_B 6970,3868 r0 bottom value=100pF
C87 "GRT188R61H225ME13D" FP-C0603C-CF-IPC_B 1415,3732 r180 bottom value=2.2μF
C88 "GRT188R61H225ME13D" FP-C0603C-CF-IPC_B 5455,3637 r90 bottom value=2.2μF
C89 "GRT188R61H225ME13D" FP-C0603C-CF-IPC_B 1545,3635 r270 bottom value=2.2μF
C90 "CL10C560JB8NNNC" FP-C0603C-CF-IPC_B 5585,3596 r0 bottom value=56pF
C91 "CL31B106KAHSFNE" FP-CL31-IPC_B 2070,3595 r180 bottom value=10μF
C92 "CL31B106KAHSFNE" FP-CL31-IPC_B 1875,3595 r180 bottom value=10μF
C93 "GRT188R61H225ME13D" FP-C0603C-CF-IPC_B 5585,3528 r0 bottom value=2.2μF
C94 "CL10C560JB8NNNC" FP-C0603C-CF-IPC_B 6765,3500 r0 bottom value=56pF
C95 "GRT188R61H225ME13D" FP-C0603C-CF-IPC_B 6625,3500 r0 bottom value=2.2μF
C96 "CL31B106KAHSFNE" FP-CL31-IPC_B 2070,3495 r180 bottom value=10μF
C97 "CL31B106KAHSFNE" FP-CL31-IPC_B 1875,3495 r180 bottom value=10μF
C98 "CL31B106KAHSFNE" FP-CL31-IPC_B 5170,3420 r0 bottom value=10μF
C99 "CL31B106KAHSFNE" FP-CL31-IPC_B 4980,3420 r0 bottom value=10μF
C100 "CL31B106KAHSFNE" FP-CL31-IPC_B 5170,3320 r0 bottom value=10μF
C101 "CL31B106KAHSFNE" FP-CL31-IPC_B 4980,3320 r0 bottom value=10μF
C102 "CL10C560JB8NNNC" FP-C0603C-CF-IPC_B 6790,3261 r180 bottom value=56pF
C103 "CL10C560JB8NNNC" FP-C0603C-CF-IPC_B 6790,3192 r180 bottom value=56pF
C104 "C0603C104K3RACTU" FP-C0603C-CF-IPC_B 6650,3192 r0 bottom value=0.10μF
C105 "CL31B106KAHSFNE" FP-CL31-IPC_B 5880,3152.8 r180 bottom value=10μF
C106 "CL31B106KAHSFNE" FP-CL31-IPC_B 1220,3155 r180 bottom value=10μF
C107 "CL10C560JB8NNNC" FP-C0603C-CF-IPC_B 6790,3123 r180 bottom value=56pF
C108 "CL10C560JB8NNNC" FP-C0603C-CF-IPC_B 6790,3054 r180 bottom value=56pF
C109 "C0603C104K3RACTU" FP-C0603C-CF-IPC_B 6650,3054 r0 bottom value=0.10μF
C110 "GRT188R61H225ME13D" FP-C0603C-CF-IPC_B 1415,3032 r180 bottom value=2.2μF
C111 "C0603C104K3RACTU" FP-C0603C-CF-IPC_B 7065,2986.42 r270 bottom value=0.10μF
C112 "CL31B106KAHSFNE" FP-CL31-IPC_B 740,2960 r270 bottom value=10μF
C113 "CL10C560JB8NNNC" FP-C0603C-CF-IPC_B 6790,2985 r180 bottom value=56pF
C114 "C0603C104K3RACTU" FP-C0603C-CF-IPC_B 6650,2985 r180 bottom value=0.10μF
C115 "CL10C560JB8NNNC" FP-C0603C-CF-IPC_B 1415,2964 r180 bottom value=56pF
C116 "CL10C560JB8NNNC" FP-C0603C-CF-IPC_B 5585,2964 r0 bottom value=56pF
C117 "GRT188R61H225ME13D" FP-C0603C-CF-IPC_B 5455,2937 r90 bottom value=2.2μF
C118 "GRT188R61H225ME13D" FP-C0603C-CF-IPC_B 1545,2935 r270 bottom value=2.2μF
C119 "CL10C560JB8NNNC" FP-C0603C-CF-IPC_B 6790,2915 r180 bottom value=56pF
C120 "CL10C560JB8NNNC" FP-C0603C-CF-IPC_B 1415,2896 r180 bottom value=56pF
C121 "CL10C560JB8NNNC" FP-C0603C-CF-IPC_B 5585,2896 r0 bottom value=56pF
C122 "CL31B106KAHSFNE" FP-CL31-IPC_B 2070,2895 r180 bottom value=10μF
C123 "CL31B106KAHSFNE" FP-CL31-IPC_B 1875,2895 r180 bottom value=10μF
C124 "GRT188R61H225ME13D" FP-C0603C-CF-IPC_B 5585,2828 r0 bottom value=2.2μF
C125 "CL31B106KAHSFNE" FP-CL31-IPC_B 740,2760 r90 bottom value=10μF
C126 "C0603C104K3RACTU" FP-C0603C-CF-IPC_B 7030,2785 r0 bottom value=0.10μF
C127 "CL31B106KAHSFNE" FP-CL31-IPC_B 2070,2795 r180 bottom value=10μF
C128 "CL31B106KAHSFNE" FP-CL31-IPC_B 1875,2795 r180 bottom value=10μF
C129 "C0603C104K3RACTU" FP-C0603C-CF-IPC_B 7030,2716 r0 bottom value=0.10μF
C130 "CL31B106KAHSFNE" FP-CL31-IPC_B 5170,2720 r0 bottom value=10μF
C131 "CL31B106KAHSFNE" FP-CL31-IPC_B 4980,2720 r0 bottom value=10μF
C132 "GRT188R61H225ME13D" FP-C0603C-CF-IPC_B 7490,2625 r0 bottom value=2.2μF
C133 "CL31B106KAHSFNE" FP-CL31-IPC_B 5170,2620 r0 bottom value=10μF
C134 "CL31B106KAHSFNE" FP-CL31-IPC_B 4980,2620 r0 bottom value=10μF
C135 "CL31B106KAHSFNE" FP-CL31-IPC_B 5880,2452.8 r180 bottom value=10μF
C136 "CL31B106KAHSFNE" FP-CL31-IPC_B 1220,2455 r180 bottom value=10μF
C137 "GRT188R61H225ME13D" FP-C0603C-CF-IPC_B 1415,2332 r180 bottom value=2.2μF
C138 "CL10C560JB8NNNC" FP-C0603C-CF-IPC_B 1415,2264 r180 bottom value=56pF
C139 "CL10C560JB8NNNC" FP-C0603C-CF-IPC_B 5585,2264 r0 bottom value=56pF
C140 "GRT188R61H225ME13D" FP-C0603C-CF-IPC_B 5455,2237 r90 bottom value=2.2μF
C141 "GRT188R61H225ME13D" FP-C0603C-CF-IPC_B 1545,2235 r270 bottom value=2.2μF
C142 "CL10C560JB8NNNC" FP-C0603C-CF-IPC_B 5585,2196 r0 bottom value=56pF
C143 "CL31B106KAHSFNE" FP-CL31-IPC_B 2070,2195 r180 bottom value=10μF
C144 "CL31B106KAHSFNE" FP-CL31-IPC_B 1875,2195 r180 bottom value=10μF
C145 "GRT188R61H225ME13D" FP-C0603C-CF-IPC_B 5585,2128 r0 bottom value=2.2μF
C146 "CL31B106KAHSFNE" FP-CL31-IPC_B 2070,2095 r180 bottom value=10μF
C147 "CL31B106KAHSFNE" FP-CL31-IPC_B 1875,2095 r180 bottom value=10μF
C148 "CL31B106KAHSFNE" FP-CL31-IPC_B 7140,1965 r270 bottom value=10μF
C149 "CL31B106KAHSFNE" FP-CL31-IPC_B 6770,1965 r270 bottom value=10μF
C150 "CL31B106KAHSFNE" FP-CL31-IPC_B 5170,2020 r0 bottom value=10μF
C151 "CL31B106KAHSFNE" FP-CL31-IPC_B 4980,2020 r0 bottom value=10μF
C152 "CL31B106KAHSFNE" FP-CL31-IPC_B 5170,1920 r0 bottom value=10μF
C153 "CL31B106KAHSFNE" FP-CL31-IPC_B 4980,1920 r0 bottom value=10μF
C154 "CL31B106KAHSFNE" FP-CL31-IPC_B 7140,1765 r90 bottom value=10μF
C155 "CL31B106KAHSFNE" FP-CL31-IPC_B 6770,1765 r90 bottom value=10μF
C156 "CL31B106KAHSFNE" FP-CL31-IPC_B 5880,1752.8 r180 bottom value=10μF
C157 "CL31B106KAHSFNE" FP-CL31-IPC_B 1220,1755 r180 bottom value=10μF
C158 "C0603C102K5RACAUTO" FP-C0603C-CF-IPC_B 6160,1543 r180 bottom value=1nF
C159 "CL31B475KBHNFNE" FP-CL31-IPC_C 5730,1425 r180 bottom value=4.7μF
C160 "CL10C560JB8NNNC" FP-C0603C-CF-IPC_B 6160,1407 r0 bottom value=56pF
C161 "CL31B475KBHNFNE" FP-CL31-IPC_C 5340,1335 r270 bottom value=4.7μF
C162 "CL31B475KBHNFNE" FP-CL31-IPC_C 5220,1335 r90 bottom value=4.7μF
C163 "CL31B475KBHNFNE" FP-CL31-IPC_C 3950,1335 r270 bottom value=4.7μF
C164 "CL31B475KBHNFNE" FP-CL31-IPC_C 3830,1335 r90 bottom value=4.7μF
C165 "CL31B475KBHNFNE" FP-CL31-IPC_C 2560,1335 r270 bottom value=4.7μF
C166 "CL31B475KBHNFNE" FP-CL31-IPC_C 2440,1335 r90 bottom value=4.7μF
C167 "C0603C104K3RACTU" FP-C0603C-CF-IPC_B 7800,1285 r180 bottom value=0.10μF
C168 "C0603C331JAGAC7867" FP-C0603C-CF-IPC_B 7800,1215 r180 bottom value=330pF
C169 "C0603C472K3RAC7867" FP-C0603C-CF-IPC_B 6960,1194 r180 bottom value=4.7nF
C170 "06035A180JAT2A" FP-C0603C-CF-IPC_B 7200,1126 r180 bottom value=18pF
C171 "C0603C104K3RACTU" FP-C0603C-CF-IPC_B 7200,990 r0 bottom value=0.10μF
C172 "C0603C104K3RACTU" FP-C0603C-CF-IPC_B 6960,990 r0 bottom value=0.10μF
C173 "C0603C470J1GACTU" FP-C0603C-CF-IPC_B 7620,865 r90 bottom value=47pF
C174 "C0603C331JAGAC7867" FP-C0603C-CF-IPC_B 7290,865 r90 bottom value=330pF
C175 "C0603C470J1GACTU" FP-C0603C-CF-IPC_B 7620,745 r90 bottom value=47pF
C176 "C0603C331JAGAC7867" FP-C0603C-CF-IPC_B 7290,745 r90 bottom value=330pF
C177 "C0603C104K3RACTU" FP-C0603C-CF-IPC_B 7680,647 r0 bottom value=0.10μF
C178 "C0603C331JAGAC7867" FP-C0603C-CF-IPC_B 7800,578 r0 bottom value=330pF
C179 "C0603C104K3RACTU" FP-C0603C-CF-IPC_B 7680,578 r0 bottom value=0.10μF
C180 "C0603C104K3RACTU" FP-C0603C-CF-IPC_B 7800,508 r0 bottom value=0.10μF
C181 "C0603C104K3RACTU" FP-C0603C-CF-IPC_B 7680,508 r0 bottom value=0.10μF
C182 "CL21B105KBFNNNE" FP-CL21-IPC_A 5880,285 r180 bottom value=1μF
C183 "CL31B106KAHSFNE" FP-CL31-IPC_B 5855,175 r0 bottom value=10μF
C184 "CL31B106KAHSFNE" FP-CL31-IPC_B 6875,80 r0 bottom value=10μF
D1 "CMD17-21VRD/TR8" FP-LTST-C171GKT-MFG-RED 7420,3012 r0 top value=RED
D2 "LTST-C171KSKT" FP-LTST-C171GKT-MFG-YELLOW 7420,2930 r0 top value=YELLOW
D3 "LTST-C171GKT" FP-LTST-C171GKT-MFG 7420,2848 r0 top value=GREEN
D4 "SMD26PL-TP" ONSC-SOD-123FL-2-498-01_V 5800.63,1430 r0 top value=N/A
D5 "CUS520,H3F" FP-USC-MFG 6097,1430 r0 top value=N/A
D6 "LTST-C171GKT" FP-LTST-C171GKT-MFG 6645,1315 r0 top value=GREEN
D7 "LTST-C171GKT" FP-LTST-C171GKT-MFG 6645,1230 r0 top value=GREEN
D8 "LTST-C171GKT" FP-LTST-C171GKT-MFG 6645,1145 r0 top value=GREEN
D9 "LTST-C171GKT" FP-LTST-C171GKT-MFG 6645,1065 r0 top value=GREEN
D10 "BAS40DW-04-TP" SOT65P222X120-6N 7550,1020 r90 top value=N/A
D11 "BAS40DW-04-TP" SOT65P222X120-6N 7550,840 r90 top value=N/A
D12 "BAS40DW-04-TP" SOT65P222X120-6N 7550,660 r90 top value=N/A
D13 "APTR3216-VFX" FP-APTR3216SECK-MFG 6216.53,3700 r180 bottom value=PURPLE
D14 "APTR3216-VFX" FP-APTR3216SECK-MFG 783.47,3700 r180 bottom value=PURPLE
D15 "APTR3216-VFX" FP-APTR3216SECK-MFG 6216.53,2300 r180 bottom value=PURPLE
D16 "APTR3216-VFX" FP-APTR3216SECK-MFG 783.47,2300 r180 bottom value=PURPLE
D17 "SMD26PL-TP" ONSC-SOD-123FL-2-498-01_V 7935,2190 r90 bottom value=N/A
D18 "SMD26PL-TP" ONSC-SOD-123FL-2-498-01_V 7935,1575 r90 bottom value=N/A
D19 "SMD26PL-TP" ONSC-SOD-123FL-2-498-01_V 5865,385 r0 bottom value=N/A
HS1 "LA 6 150 12" "LA 6 150 12" 3500,3000 r180 bottom locked value=N/A
J1 "1755778" 1755778 6750,7835 r180 top value=N/A
J2 "7460307" 7460307 2110,7400 r0 top value=N/A
J3 "7460307" 7460307 4890,7400 r0 top value=N/A
J4 "L717SDE09PA4CH4RC309" L717SDE09PA4CH4RC309 7630,5020 r90 top value=N/A
J5 "0734151471" FP-73415-1471-MFG 2900,3800 r0 top value=N/A
J6 "0734151471" FP-73415-1471-MFG 3500,3800 r0 top value=N/A
J7 "0734151471" FP-73415-1471-MFG 4100,3800 r0 top value=N/A
J8 "61301221121" FP-61301221121-MFG 7887,3400 r270 top value=N/A
J9 "640456-2" TECO-640456-2_V 7887,2930 r90 top value=N/A
J10 "640456-2" TECO-640456-2_V 7887,2625 r90 top value=N/A
J11 "1755736" 1755736 7837,2200 r90 top value=N/A
J12 "0734151471" FP-73415-1471-MFG 2900,2200 r0 top value=N/A
J13 "0734151471" FP-73415-1471-MFG 3500,2200 r0 top value=N/A
J14 "0734151471" FP-73415-1471-MFG 4100,2200 r0 top value=N/A
J15 "1755736" 1755736 7837,1585 r90 top value=N/A
J16 "61200621621" 61200621621 7810,890 r270 top value=N/A
J17 "7460307" 7460307 2110,600 r0 top value=N/A
J18 "7460307" 7460307 3500,600 r0 top value=N/A
J19 "7460307" 7460307 4890,600 r0 top value=N/A
J20 "PJ-102AH" CUI-PJ-102B_V 7170,428.11 r270 top value=N/A
L1 "744226S" WE-SL2 1145,3300 r270 top value=10μH
L2 "744226S" WE-SL2 5855,3300 r270 top value=10μH
L3 "744226S" WE-SL2 1145,2600 r270 top value=10μH
L4 "744226S" WE-SL2 5855,2600 r270 top value=10μH
L5 "744226S" WE-SL2 1145,1900 r270 top value=10μH
L6 "744226S" WE-SL2 5855,1900 r270 top value=10μH
L7 "MSD7342-682MLC" MSD7342682MLC 5885,323.46 r90 top value=6.8μH
L8 "NRS5040T3R3NMGJ" FP-NR5040-H_4_1-MFG 5930,1490 r180 bottom value=3.3μH
MH1 "MH_M4_P" MH_M4_P 7750,7750 r180 bottom locked value=N/A
MH2 "MH_M4_P" MH_M4_P 250,7750 r180 bottom value=N/A
MH3 "MH_M4_P" MH_M4_P 7750,250 r180 bottom locked value=N/A
MH4 "MH_M4_P" MH_M4_P 250,250 r180 bottom value=N/A
Q1 "SI7461DP-T1-E3" FP-S17-0173-SINGLE-MFG 5847.72,1185.58 r270 top value=N/A
Q2 "BC817-16LT3G" ONSC-SOT-23-3-318-08_V 7050,1120 r0 top value=N/A
Q3 "CCB021M12FM3" FM3_SIX-PACK_3PHASE_CRW 3500,3000 r0 bottom value=N/A
Q4 "MJD44H11T4G" ONSC-DPAK-3-369C-01_V 7615,2199.76 r90 bottom value=N/A
Q5 "MJD44H11T4G" ONSC-DPAK-3-369C-01_V 7615,1585 r90 bottom value=N/A
Q6 "DMT12H007LPS-13" FP-PowerDI5060-8-MFG 6910,685 r90 bottom value=N/A
Q7 "DMT12H007LPS-13" FP-PowerDI5060-8-MFG 6910,435 r90 bottom value=N/A
R1 "CRGP2512F220K" FP-CRGP2512-IPC_C 2900,7650 r180 top value=220kΩ
R2 "CRGP2512F220K" FP-CRGP2512-IPC_C 3300,7650 r180 top value=220kΩ
R3 "CRGP2512F220K" FP-CRGP2512-IPC_C 3700,7650 r180 top value=220kΩ
R4 "CRGP2512F220K" FP-CRGP2512-IPC_C 4100,7650 r180 top value=220kΩ
R5 "CRGP2512F220K" FP-CRGP2512-IPC_C 2900,7450 r180 top value=220kΩ
R6 "CRGP2512F220K" FP-CRGP2512-IPC_C 3300,7450 r180 top value=220kΩ
R7 "CRGP2512F220K" FP-CRGP2512-IPC_C 3700,7450 r180 top value=220kΩ
R8 "CRGP2512F220K" FP-CRGP2512-IPC_C 4100,7450 r180 top value=220kΩ
R9 "CRGP2512F220K" FP-CRGP2512-IPC_C 2900,7250 r180 top value=220kΩ
R10 "CRGP2512F220K" FP-CRGP2512-IPC_C 3300,7250 r180 top value=220kΩ
R11 "CRGP2512F220K" FP-CRGP2512-IPC_C 3700,7250 r180 top value=220kΩ
R12 "CRGP2512F220K" FP-CRGP2512-IPC_C 4100,7250 r180 top value=220kΩ
R13 "TNPW1206249KBEEA" RESC3216X65X50NL15T25 6580,7150 r270 top value=249kΩ
R14 "TNPW1206249KBEEA" RESC3216X65X50NL15T25 6940,7150 r270 top value=249kΩ
R15 "TNPW1206249KBEEA" RESC3216X65X50NL15T25 7300,7150 r270 top value=249kΩ
R16 "TNPW1206249KBEEA" RESC3216X65X50NL15T25 7660,7150 r270 top value=249kΩ
R17 "TNPW1206249KBEEA" RESC3216X65X50NL15T25 6580,6960 r270 top value=249kΩ
R18 "TNPW1206249KBEEA" RESC3216X65X50NL15T25 6940,6960 r270 top value=249kΩ
R19 "TNPW1206249KBEEA" RESC3216X65X50NL15T25 7300,6960 r270 top value=249kΩ
R20 "TNPW1206249KBEEA" RESC3216X65X50NL15T25 7660,6960 r270 top value=249kΩ
R21 "TNPW1206249KBEEA" RESC3216X65X50NL15T25 6580,6770 r270 top value=249kΩ
R22 "TNPW1206249KBEEA" RESC3216X65X50NL15T25 6940,6770 r270 top value=249kΩ
R23 "TNPW1206249KBEEA" RESC3216X65X50NL15T25 7300,6770 r270 top value=249kΩ
R24 "TNPW1206249KBEEA" RESC3216X65X50NL15T25 7660,6770 r270 top value=249kΩ
R25 "TNPW1206249KBEEA" RESC3216X65X50NL15T25 6580,6580 r270 top value=249kΩ
R26 "TNPW1206249KBEEA" RESC3216X65X50NL15T25 6940,6580 r270 top value=249kΩ
R27 "TNPW1206249KBEEA" RESC3216X65X50NL15T25 7300,6580 r270 top value=249kΩ
R28 "TNPW1206249KBEEA" RESC3216X65X50NL15T25 7660,6580 r270 top value=249kΩ
R29 "TNPW1206249KBEEA" RESC3216X65X50NL15T25 6580,6390 r270 top value=249kΩ
R30 "TNPW1206249KBEEA" RESC3216X65X50NL15T25 6940,6390 r270 top value=249kΩ
R31 "TNPW1206249KBEEA" RESC3216X65X50NL15T25 7300,6390 r270 top value=249kΩ
R32 "TNPW1206249KBEEA" RESC3216X65X50NL15T25 7660,6390 r270 top value=249kΩ
R33 "TNPW1206249KBEEA" RESC3216X65X50NL15T25 6580,6200 r270 top value=249kΩ
R34 "TNPW1206249KBEEA" RESC3216X65X50NL15T25 6940,6200 r270 top value=249kΩ
R35 "TNPW1206249KBEEA" RESC3216X65X50NL15T25 7300,6200 r270 top value=249kΩ
R36 "TNPW1206249KBEEA" RESC3216X65X50NL15T25 7660,6200 r270 top value=249kΩ
R37 "RC0603FR-074K99L" FP-MCR03-IPC_B 6580,6040 r270 top value=4.99kΩ
R38 "ERJ-PB3B3741V" FP-MCR03-IPC_B 6700,6040 r90 top value=3.74kΩ
R39 "RC0603FR-074K99L" FP-MCR03-IPC_B 6940,6040 r270 top value=4.99kΩ
R40 "ERJ-PB3B1801V" FP-MCR03-IPC_B 7060,6040 r270 top value=1.8kΩ
R41 "RC0603FR-074K99L" FP-MCR03-IPC_B 7300,6040 r270 top value=4.99kΩ
R42 "ERJ-PB3B1801V" FP-MCR03-IPC_B 7420,6040 r270 top value=1.8kΩ
R43 "RC0603FR-074K99L" FP-MCR03-IPC_B 7660,6040 r270 top value=4.99kΩ
R44 "ERJ-PB3B1801V" FP-MCR03-IPC_B 7780,6040 r270 top value=1.8kΩ
R45 "ERJ-3EKF49R9V" FP-MCR03-IPC_B 6790,4566 r0 top value=49.9Ω
R46 "ERJ-3EKF49R9V" FP-MCR03-IPC_B 6790,4499 r0 top value=49.9Ω
R47 "ERA3AEB132V" FP-MCR03-IPC_B 5656,4465 r90 top value=1.3kΩ
R48 "RC1608F1542CS" FP-MCR03-IPC_B 5724,4465 r90 top value=15.4kΩ
R49 "CRCW06034K70FKTA" FP-MCR03-IPC_B 5860,4465 r270 top value=4.7kΩ
R50 "ERJ3EKF1002V" FP-MCR03-IPC_B 5928,4465 r270 top value=10kΩ
R51 "CRCW06030000Z0EB" FP-MCR03-IPC_B 5995,4465 r90 top value=0Ω
R52 "ERJ3EKF1002V" FP-MCR03-IPC_B 6062,4465 r90 top value=10kΩ
R53 "ERJ-3EKF49R9V" FP-MCR03-IPC_B 6790,4432 r0 top value=49.9Ω
R54 "ERJ-3EKF49R9V" FP-MCR03-IPC_B 6790,4365 r0 top value=49.9Ω
R55 "RT0603DRE072KL" FP-MCR03-IPC_B 7210,4236 r180 top value=2kΩ
R56 "RT0603DRE072KL" FP-MCR03-IPC_B 7210,4100 r180 top value=2kΩ
R57 "ERJ-3EKF49R9V" FP-MCR03-IPC_B 6790,4042 r0 top value=49.9Ω
R58 "CRCW06030000Z0EB" FP-MCR03-IPC_B 7210,3964 r180 top value=0Ω
R59 "CRCW06030000Z0EB" FP-MCR03-IPC_B 7210,3896 r180 top value=0Ω
R60 "RCWE1210R910FKEA" RESC3125X70X40NL20T20 4870,3695 r180 top value=0.91Ω
R61 "CRCW12100000Z0EAHP" RESC3125X70X40NL20T20 2130,3695 r0 top value=0Ω
R62 "ERJ-3EKF49R9V" FP-MCR03-IPC_B 5585,3596 r180 top value=49.9Ω
R63 "RCWE1210R910FKEA" RESC3125X70X40NL20T20 2130,3565 r0 top value=0.91Ω
R64 "CRCW12100000Z0EAHP" RESC3125X70X40NL20T20 4870,3565 r180 top value=0Ω
R65 "ERJ-3EKF49R9V" FP-MCR03-IPC_B 6790,3480 r180 top value=49.9Ω
R66 "ERA3AEB132V" FP-MCR03-IPC_B 6290,3386 r180 top value=1.3kΩ
R67 "ERJ3EKF1002V" FP-MCR03-IPC_B 6290,3319 r0 top value=10kΩ
R68 "ERJ-3EKF49R9V" FP-MCR03-IPC_B 6790,3256 r0 top value=49.9Ω
R69 "ERJ-3EKF49R9V" FP-MCR03-IPC_B 6790,3189 r0 top value=49.9Ω
R70 "ERJ-3EKF49R9V" FP-MCR03-IPC_B 6790,3122 r0 top value=49.9Ω
R71 "ERJ3EKF1002V" FP-MCR03-IPC_B 6290,3114 r180 top value=10kΩ
R72 "ERJ-3EKF49R9V" FP-MCR03-IPC_B 6790,3055 r0 top value=49.9Ω
R73 "ERA3AEB132V" FP-MCR03-IPC_B 6290,3046 r0 top value=1.3kΩ
R74 "RCWE1210R910FKEA" RESC3125X70X40NL20T20 4870,2995 r180 top value=0.91Ω
R75 "CRCW12100000Z0EAHP" RESC3125X70X40NL20T20 2130,2995 r0 top value=0Ω
R76 "ERJ-3EKF49R9V" FP-MCR03-IPC_B 6790,2988 r0 top value=49.9Ω
R77 "ERJ-3EKF49R9V" FP-MCR03-IPC_B 1415,2964 r0 top value=49.9Ω
R78 "ERJ-3EKF49R9V" FP-MCR03-IPC_B 5585,2964 r180 top value=49.9Ω
R79 "ERJ-3EKF49R9V" FP-MCR03-IPC_B 6790,2921 r0 top value=49.9Ω
R80 "ERJ-3EKF49R9V" FP-MCR03-IPC_B 1415,2896 r0 top value=49.9Ω
R81 "ERJ-3EKF49R9V" FP-MCR03-IPC_B 5585,2896 r180 top value=49.9Ω
R82 "RCWE1210R910FKEA" RESC3125X70X40NL20T20 2130,2865 r0 top value=0.91Ω
R83 "CRCW12100000Z0EAHP" RESC3125X70X40NL20T20 4870,2865 r180 top value=0Ω
R84 "RC2010FK-07100RL" RESC2010(5025)_N 6510,2515 r0 top value=100Ω
R85 "RT0603DRE072KL" FP-MCR03-IPC_B 6685,2535 r0 top value=2kΩ
R86 "RC2010FK-07100RL" RESC2010(5025)_N 6510,2385 r0 top value=100Ω
R87 "RT0603DRE072KL" FP-MCR03-IPC_B 6685,2385 r0 top value=2kΩ
R88 "RCWE1210R910FKEA" RESC3125X70X40NL20T20 4870,2295 r180 top value=0.91Ω
R89 "RCWE1210R910FKEA" RESC3125X70X40NL20T20 2130,2165 r0 top value=0.91Ω
R90 "RC2010FK-07100RL" RESC2010(5025)_N 6510,2255 r0 top value=100Ω
R91 "ERJ-3EKF49R9V" FP-MCR03-IPC_B 1415,2264 r0 top value=49.9Ω
R92 "ERJ-3EKF49R9V" FP-MCR03-IPC_B 5585,2264 r180 top value=49.9Ω
R93 "RT0603DRE072KL" FP-MCR03-IPC_B 6685,2235 r0 top value=2kΩ
R94 "ERJ-3EKF49R9V" FP-MCR03-IPC_B 5585,2196 r180 top value=49.9Ω
R95 "CRCW12100000Z0EAHP" RESC3125X70X40NL20T20 2130,2295 r0 top value=0Ω
R96 "CRCW12100000Z0EAHP" RESC3125X70X40NL20T20 4870,2165 r180 top value=0Ω
R97 "ERJ3EKF1002V" FP-MCR03-IPC_B 7050,1432 r0 top value=10kΩ
R98 "RC0603FR-07100KL" FP-MCR03-IPC_B 5635,1430 r0 top value=100kΩ
R99 "RC0603FR-07100KL" FP-MCR03-IPC_B 5953.62,1430 r180 top value=100kΩ
R100 "ERJ-3EKF1653V" FP-MCR03-IPC_B 6222,1430 r0 top value=165kΩ
R101 "RC0603FR-07120KL" FP-MCR03-IPC_B 7170,1363 r180 top value=120kΩ
R102 "ERJ3EKF1002V" FP-MCR03-IPC_B 7050,1295 r180 top value=10kΩ
R103 "ERJ3EKF1002V" FP-MCR03-IPC_B 7170,1227 r180 top value=10kΩ
R104 "RC0603JR-0720RL" FP-MCR03-IPC_B 7170,1159 r0 top value=20Ω
R105 "ERJ3EKF1002V" FP-MCR03-IPC_B 7170,1091 r180 top value=10kΩ
R106 "ERJ3EKF1002V" FP-MCR03-IPC_B 6035,1085 r0 top value=10kΩ
R107 "RC0603FR-07470KL" FP-MCR03-IPC_B 7320,1022 r0 top value=470kΩ
R108 "RC0603FR-0756KL" FP-MCR03-IPC_B 6034.41,1017 r180 top value=56kΩ
R109 "RMCF0603FT45K3" FP-MCR03-IPC_B 6180,1017 r180 top value=45.3kΩ
R110 "RC0603FR-07120KL" FP-MCR03-IPC_B 7170,954 r0 top value=120kΩ
R111 "ERJ-3EKF2003V" FP-MCR03-IPC_B 6510,614 r180 top value=200kΩ
R112 "RC0603FR-07100KL" FP-MCR03-IPC_B 6195,530 r90 top value=100kΩ
R113 "ERJ3EKF1002V" FP-MCR03-IPC_B 6331,530 r270 top value=10kΩ
R114 "RC0603FR-07100KL" FP-MCR03-IPC_B 6510,546 r180 top value=100kΩ
R115 "ERJ-3EKF2202V" FP-MCR03-IPC_B 6905,458 r180 top value=22kΩ
R116 "RC0603JR-072M7L" FP-MCR03-IPC_B 6510,410 r0 top value=2.7MΩ
R117 "RC0603FR-07100KL" FP-MCR03-IPC_B 6905,390 r0 top value=100kΩ
R118 "RC0603JR-072M7L" FP-MCR03-IPC_B 6510,342 r180 top value=2.7MΩ
R119 "RC0603FR-0756KL" FP-MCR03-IPC_B 6100,135 r270 top value=56kΩ
R120 "ERJ3EKF1002V" FP-MCR03-IPC_B 6167,135 r90 top value=10kΩ
R121 "RMCF0603FT45K3" FP-MCR03-IPC_B 6234,135 r90 top value=45.3kΩ
R122 "TNPW1206249KBEEA" RESC3216X65X50NL15T25 7660,7150 r270 bottom value=249kΩ
R123 "TNPW1206249KBEEA" RESC3216X65X50NL15T25 7300,7150 r270 bottom value=249kΩ
R124 "TNPW1206249KBEEA" RESC3216X65X50NL15T25 6940,7150 r270 bottom value=249kΩ
R125 "TNPW1206249KBEEA" RESC3216X65X50NL15T25 6580,7150 r270 bottom value=249kΩ
R126 "TNPW1206249KBEEA" RESC3216X65X50NL15T25 7660,6960 r270 bottom value=249kΩ
R127 "TNPW1206249KBEEA" RESC3216X65X50NL15T25 7300,6960 r270 bottom value=249kΩ
R128 "TNPW1206249KBEEA" RESC3216X65X50NL15T25 6940,6960 r270 bottom value=249kΩ
R129 "TNPW1206249KBEEA" RESC3216X65X50NL15T25 6580,6960 r270 bottom value=249kΩ
R130 "TNPW1206249KBEEA" RESC3216X65X50NL15T25 7660,6770 r270 bottom value=249kΩ
R131 "TNPW1206249KBEEA" RESC3216X65X50NL15T25 7300,6770 r270 bottom value=249kΩ
R132 "TNPW1206249KBEEA" RESC3216X65X50NL15T25 6940,6770 r270 bottom value=249kΩ
R133 "TNPW1206249KBEEA" RESC3216X65X50NL15T25 6580,6770 r270 bottom value=249kΩ
R134 "TNPW1206249KBEEA" RESC3216X65X50NL15T25 7660,6580 r270 bottom value=249kΩ
R135 "TNPW1206249KBEEA" RESC3216X65X50NL15T25 7300,6580 r270 bottom value=249kΩ
R136 "TNPW1206249KBEEA" RESC3216X65X50NL15T25 6940,6580 r270 bottom value=249kΩ
R137 "TNPW1206249KBEEA" RESC3216X65X50NL15T25 6580,6580 r270 bottom value=249kΩ
R138 "TNPW1206249KBEEA" RESC3216X65X50NL15T25 7660,6390 r270 bottom value=249kΩ
R139 "TNPW1206249KBEEA" RESC3216X65X50NL15T25 7300,6390 r270 bottom value=249kΩ
R140 "TNPW1206249KBEEA" RESC3216X65X50NL15T25 6940,6390 r270 bottom value=249kΩ
R141 "TNPW1206249KBEEA" RESC3216X65X50NL15T25 6580,6390 r270 bottom value=249kΩ
R142 "TNPW1206249KBEEA" RESC3216X65X50NL15T25 7660,6200 r270 bottom value=249kΩ
R143 "TNPW1206249KBEEA" RESC3216X65X50NL15T25 7300,6200 r270 bottom value=249kΩ
R144 "TNPW1206249KBEEA" RESC3216X65X50NL15T25 6940,6200 r270 bottom value=249kΩ
R145 "TNPW1206249KBEEA" RESC3216X65X50NL15T25 6580,6200 r270 bottom value=249kΩ
R146 "ERJ-PB3B1801V" FP-MCR03-IPC_B 7780,6040 r90 bottom value=1.8kΩ
R147 "RC0603FR-074K99L" FP-MCR03-IPC_B 7540,6040 r270 bottom value=4.99kΩ
R148 "ERJ-PB3B1801V" FP-MCR03-IPC_B 7420,6040 r90 bottom value=1.8kΩ
R149 "RC0603FR-074K99L" FP-MCR03-IPC_B 7180,6040 r270 bottom value=4.99kΩ
R150 "ERJ-PB3B1801V" FP-MCR03-IPC_B 7060,6040 r90 bottom value=1.8kΩ
R151 "RC0603FR-074K99L" FP-MCR03-IPC_B 6820,6040 r270 bottom value=4.99kΩ
R152 "ERJ-PB3B3741V" FP-MCR03-IPC_B 6700,6040 r270 bottom value=3.74kΩ
R153 "RC0603FR-074K99L" FP-MCR03-IPC_B 6460,6040 r270 bottom value=4.99kΩ
R154 "RMCF0603FT1K33" FP-MCR03-IPC_B 7230,4548 r180 bottom value=1.33kΩ
R155 "RMCF0603FT7K15" FP-MCR03-IPC_B 7230,4480 r180 bottom value=7.15kΩ
R156 "RC0603JR-07120RL" FP-MCR03-IPC_B 7930,4395 r90 bottom value=120Ω
R157 "ERJ3EKF1002V" FP-MCR03-IPC_B 6012,4320 r90 bottom value=10kΩ
R158 "ERJ-3EKF9762V" FP-MCR03-IPC_B 5945,4320 r90 bottom value=97.6kΩ
R159 "RMCF0603FT249K" FP-MCR03-IPC_B 5878,4320 r270 bottom value=249kΩ
R160 "ERJ3EKF1002V" FP-MCR03-IPC_B 5810,4320 r90 bottom value=10kΩ
R161 "RC0603FR-13330RL" FP-MCR03-IPC_B 5743,4320 r90 bottom value=330Ω
R162 "CRCW060320K0FKTA" FP-MCR03-IPC_B 5675,4320 r90 bottom value=20kΩ
R163 "ERJ3EKF1002V" FP-MCR03-IPC_B 5608,4320 r90 bottom value=10kΩ
R164 "ERA3AEB4021V" FP-MCR03-IPC_B 7230,4343 r0 bottom value=4.02kΩ
R165 "RC0603FR-077K87L" FP-MCR03-IPC_B 6970,4343 r0 bottom value=7.87kΩ
R166 "RMCF0603FT1K33" FP-MCR03-IPC_B 7230,4275 r180 bottom value=1.33kΩ
R167 "RMCF0603FT7K15" FP-MCR03-IPC_B 7230,4207 r180 bottom value=7.15kΩ
R168 "ERJ-3EKF49R9V" FP-MCR03-IPC_B 6790,4139 r0 bottom value=49.9Ω
R169 "ERA3AEB4021V" FP-MCR03-IPC_B 7230,4070 r0 bottom value=4.02kΩ
R170 "RC0603FR-077K87L" FP-MCR03-IPC_B 6970,4070 r0 bottom value=7.87kΩ
R171 "ERJ-3EKF49R9V" FP-MCR03-IPC_B 6790,4070 r0 bottom value=49.9Ω
R172 "RMCF0603FT1K33" FP-MCR03-IPC_B 7230,4003 r180 bottom value=1.33kΩ
R173 "RMCF0603FT7K15" FP-MCR03-IPC_B 7230,3936 r180 bottom value=7.15kΩ
R174 "ERA3AEB4021V" FP-MCR03-IPC_B 7230,3800 r0 bottom value=4.02kΩ
R175 "RC0603FR-077K87L" FP-MCR03-IPC_B 6970,3800 r0 bottom value=7.87kΩ
R176 "RC0603FR-07100KL" FP-MCR03-IPC_B 6625,3770 r180 bottom value=100kΩ
R177 "RC0603FR-07100KL" FP-MCR03-IPC_B 6485,3770 r180 bottom value=100kΩ
R178 "CRCW08051K00JNTA" RESC2013X50X30LL20T20 6050,3735 r180 bottom value=1kΩ
R179 "RC0603FR-07100KL" FP-MCR03-IPC_B 6625,3703 r180 bottom value=100kΩ
R180 "RC0603FR-07100KL" FP-MCR03-IPC_B 6485,3703 r180 bottom value=100kΩ
R181 "ERJ-3EKF49R9V" FP-MCR03-IPC_B 1415,3664 r0 bottom value=49.9Ω
R182 "ERJ-3EKF49R9V" FP-MCR03-IPC_B 5585,3664 r180 bottom value=49.9Ω
R183 "CRCW08051K00JNTA" RESC2013X50X30LL20T20 6050,3665 r180 bottom value=1kΩ
R184 "RC0603FR-07100KL" FP-MCR03-IPC_B 6625,3636 r180 bottom value=100kΩ
R185 "CRCW08051K00JNTA" RESC2013X50X30LL20T20 783.47,3600 r0 bottom value=1kΩ
R186 "ERJ-3EKF49R9V" FP-MCR03-IPC_B 1415,3596 r0 bottom value=49.9Ω
R187 "RC0603FR-07100KL" FP-MCR03-IPC_B 6625,3568 r180 bottom value=100kΩ
R188 "CRCW08051K00JNTA" RESC2013X50X30LL20T20 783.47,3530 r0 bottom value=1kΩ
R189 "ERJ3EKF1002V" FP-MCR03-IPC_B 6765,3430 r180 bottom value=10kΩ
R190 "RC0603FR-07680RL" FP-MCR03-IPC_B 7530,3358 r180 bottom value=680Ω
R191 "RC0603FR-07680RL" FP-MCR03-IPC_B 7530,3290 r180 bottom value=680Ω
R192 "RC0603FR-07680RL" FP-MCR03-IPC_B 7530,3222 r180 bottom value=680Ω
R193 "CRCW06030000Z0EB" FP-MCR03-IPC_B 7230,3200 r180 bottom value=0Ω
R194 "ERJ-3EKF49R9V" FP-MCR03-IPC_B 6295,3185 r0 bottom value=49.9Ω
R195 "CRCW06030000Z0EB" FP-MCR03-IPC_B 7230,3133 r180 bottom value=0Ω
R196 "CRCW06030000Z0EB" FP-MCR03-IPC_B 7230,3066 r180 bottom value=0Ω
R197 "CRCW06030000Z0EB" FP-MCR03-IPC_B 7230,2998 r180 bottom value=0Ω
R198 "ERJ-3EKF49R9V" FP-MCR03-IPC_B 6295,2975 r0 bottom value=49.9Ω
R199 "ERJ-3EKF49R9V" FP-MCR03-IPC_B 6295,2765 r0 bottom value=49.9Ω
R200 "CRCW08051K00JNTA" RESC2013X50X30LL20T20 783.47,2470 r0 bottom value=1kΩ
R201 "CRCW08051K00JNTA" RESC2013X50X30LL20T20 783.47,2400 r0 bottom value=1kΩ
R202 "CRCW08051K00JNTA" RESC2013X50X30LL20T20 6050,2335 r180 bottom value=1kΩ
R203 "CRCW08051K00JNTA" RESC2013X50X30LL20T20 6050,2265 r180 bottom value=1kΩ
R204 "ERJ-3EKF49R9V" FP-MCR03-IPC_B 1415,2196 r0 bottom value=49.9Ω
R205 "RC1206FR-07249RL" FP-MCR18-IPC_A 7610.9,1899.76 r0 bottom value=249Ω
R206 "ERJ3EKF1002V" FP-MCR03-IPC_B 6160,1475 r180 bottom value=10kΩ
R207 "RC1206FR-07249RL" FP-MCR18-IPC_A 6645,1323 r0 bottom value=249Ω
R208 "RC1206FR-07249RL" FP-MCR18-IPC_A 7610.9,1280 r0 bottom value=249Ω
R209 "ERJ3EKF3901V" FP-MCR03-IPC_B 6960,1263 r0 bottom value=3.9kΩ
R210 "RC0805FR-07499RL" FP-MCR10-IPC_A 6645,1234 r180 bottom value=499Ω
R211 "RC0603FR-07470KL" FP-MCR03-IPC_B 7200,1194 r180 bottom value=470kΩ
R212 "ERA-3AED153V" FP-MCR03-IPC_B 7080,1194 r0 bottom value=15kΩ
R213 "ERJ-6ENF2431V" FP-MCR10-IPC_A 6645,1145 r180 bottom value=2.43kΩ
R214 "ERJ3EKF1002V" FP-MCR03-IPC_B 7800,1146 r180 bottom value=10kΩ
R215 "ERJ3EKF3901V" FP-MCR03-IPC_B 7080,1126 r180 bottom value=3.9kΩ
R216 "ERJ-6ENF2431V" FP-MCR10-IPC_A 6645,1056 r0 bottom value=2.43kΩ
R217 "ERA-3AED153V" FP-MCR03-IPC_B 7200,1058 r180 bottom value=15kΩ
R218 "ERJ3EKF1002V" FP-MCR03-IPC_B 7080,1058 r0 bottom value=10kΩ
R219 "ERJ3EKF1002V" FP-MCR03-IPC_B 7080,990 r180 bottom value=10kΩ
R220 "ERJ-PB3B1212V" FP-MCR03-IPC_B 7530,907 r180 bottom value=12.1kΩ
R221 "RC0603FR-0747KL" FP-MCR03-IPC_B 7688,865 r270 bottom value=47kΩ
R222 "ERJ3EKF1002V" FP-MCR03-IPC_B 7222,865 r270 bottom value=10kΩ
R223 "ERJ-PB3B1212V" FP-MCR03-IPC_B 7530,839 r180 bottom value=12.1kΩ
R224 "ERJ-PB3B1212V" FP-MCR03-IPC_B 7530,771 r180 bottom value=12.1kΩ
R225 "RC0603FR-0747KL" FP-MCR03-IPC_B 7688,745 r90 bottom value=47kΩ
R226 "ERJ3EKF1002V" FP-MCR03-IPC_B 7222,745 r270 bottom value=10kΩ
R227 "ERJ-PB3B1212V" FP-MCR03-IPC_B 7530,703 r180 bottom value=12.1kΩ
R228 "ERJ3EKF1002V" FP-MCR03-IPC_B 7800,647 r0 bottom value=10kΩ
R229 "PE2512FKE7W0R01L" FP-RL2512-IPC_A 6875,215 r180 bottom value=10mΩ
R230 "CRGCQ0603F180K" FP-CRGCQ0603-IPC_A 5885,80 r180 bottom value=180kΩ
R231 "ERJ3EKF1002V" FP-MCR03-IPC_B 2130,2760 r0 top value=10kΩ
R232 "ERJ3EKF1002V" FP-MCR03-IPC_B 2130,3460 r0 top value=10kΩ
R233 "ERJ3EKF1002V" FP-MCR03-IPC_B 4870,3460 r180 top value=10kΩ
R234 "ERJ3EKF1002V" FP-MCR03-IPC_B 2130,2060 r0 top value=10kΩ
R235 "ERJ3EKF1002V" FP-MCR03-IPC_B 4870,2060 r180 top value=10kΩ
R236 "ERJ3EKF1002V" FP-MCR03-IPC_B 4870,2760 r180 top value=10kΩ
TP1 "5010" KSTN-5010_V 1570,7085 r0 top value=RED
TP2 "5010" KSTN-5010_V 2660,7085 r0 top value=RED
TP3 "5011" KSTN-5011_V 4350,7085 r0 top value=BLACK
TP4 "5011" KSTN-5011_V 5430,7085 r0 top value=BLACK
TP5 "5010" KSTN-5010_V 7270,2560 r0 top value=RED
TP6 "5010" KSTN-5010_V 7270,2390 r0 top value=RED
TP7 "5011" KSTN-5011_V 7270,2220 r0 top value=BLACK
TP8 "5010" KSTN-5010_V 5520,830 r0 top value=RED
TP9 "5010" KSTN-5010_V 5520,690 r0 top value=RED
TP10 "5012" KSTN-5012_V 1660,600 r0 top value=WHITE
TP11 "5012" KSTN-5012_V 3050,600 r0 top value=WHITE
TP12 "5012" KSTN-5012_V 4440,600 r0 top value=WHITE
TP13 "5011" KSTN-5011_V 5520,550 r0 top value=BLACK
TP14 "5010" KSTN-5010_V 6465,235 r0 top value=RED
TP15 "5011" KSTN-5011_V 6465,90 r0 top value=BLACK
U1 "AD8615AUJZ-REEL7" ADI-UJ-5_M 6580,5920 r180 top value=N/A
U2 "AD8615AUJZ-REEL7" ADI-UJ-5_M 6940,5920 r180 top value=N/A
U3 "AD8615AUJZ-REEL7" ADI-UJ-5_M 7300,5920 r180 top value=N/A
U4 "AD8615AUJZ-REEL7" ADI-UJ-5_M 7660,5920 r180 top value=N/A
U5 "TMDSCNCD280039C" TMDSCNCD280039C 7000,3675 r90 top locked value=N/A
U6 "TES 1-0511" TRACO-TES1-5_V 6420,4695 r270 top value=N/A
U7 "REF2033QDDCRQ1" FP-DDC0005A-MFG 7355,4545 r180 top
U8 "ISO722MDR" D0008B_L 6375,4345 r0 top value=N/A
U9 "MCP6292-E/MS" MSOP-MS8_L 5940,4325 r0 top value=N/A
U10 "TS431IYLT" SOT95P280X145-5N 5725,4325 r180 top value=N/A
U11 "LTC6992CS6-2#TRMPBF" SOT95P280X100-6N 6150,4325 r0 top value=N/A
U12 "R1SE-3.305/H2-R" FP-R1SE-0505-R-MFG 7685,4100 r90 top value=N/A
U13 "SN74LV541ATPWR" PW0020A_L 6622.8,3678.98 r180 top value=N/A
U14 "UCC5350SBD" D0008B_HV 1655,3630 r0 top value=N/A
U15 "UCC5350SBD" D0008B_HV 5345,3630 r180 top value=N/A
U16 "MGJ2D121503SC" MGJ2D121509SC 1670,3300 r0 top value=N/A
U17 "MGJ2D121503SC" MGJ2D121509SC 5330,3300 r180 top value=N/A
U18 "TLV3502AID" FP-D0008A-IPC_B 6530,3160 r0 top value=N/A
U19 "R-78E5.0-1.0" CONV_R-78E5.0-1.0 766.42,2860 r90 top value=N/A
U20 "UCC5350SBD" D0008B_HV 1655,2930 r0 top value=N/A
U21 "TLV3502AID" FP-D0008A-IPC_B 6530,2950 r0 top value=N/A
U22 "UCC5350SBD" D0008B_HV 5345,2930 r180 top value=N/A
U23 "TLV3502AID" FP-D0008A-IPC_B 6528.06,2740 r0 top value=N/A
U24 "MGJ2D121503SC" MGJ2D121509SC 1670,2600 r0 top value=N/A
U25 "MGJ2D121503SC" MGJ2D121509SC 5330,2600 r180 top value=N/A
U26 "UCC5350SBD" D0008B_HV 1655,2230 r0 top value=N/A
U27 "UCC5350SBD" D0008B_HV 5345,2230 r180 top value=N/A
U28 "MGJ2D121503SC" MGJ2D121509SC 1670,1900 r0 top value=N/A
U29 "MGJ2D121503SC" MGJ2D121509SC 5330,1900 r180 top value=N/A
U30 "R-78E3.3-1.0" CONV_R-78E3.3-1.0 6796.42,1865 r90 top value=N/A
U31 "R-78E5.0-1.0" CONV_R-78E5.0-1.0 7165,1865 r90 top value=N/A
U32 "LAH 50-P" "LAH 50-P" 2110,1300 r90 top value=N/A
U33 "LAH 50-P" "LAH 50-P" 3500,1300 r90 top value=N/A
U34 "LAH 50-P" "LAH 50-P" 4890,1300 r90 top value=N/A
U35 "LT3581EMSE#PBF" LT-MSE-16-EDP_L 6065,1245 r270 top value=N/A
U36 "LTC4368IMS-2#PBF" SOP50P490X110-10N 6710,450 r0 top value=N/A
U37 "LT3581EMSE#PBF" LT-MSE-16-EDP_L 6180,330 r270 top value=N/A
U38 "REF2033QDDCRQ1" FP-DDC0005A-MFG 7480,5815 r180 bottom
U39 "AD8615AUJZ-REEL7" ADI-UJ-5_M 7070,4510 r180 bottom value=N/A
U40 "AD8615AUJZ-REEL7" ADI-UJ-5_M 7070,4238 r180 bottom value=N/A
U41 "ISO1050DUBR" DUB0008A_M 7700,4110 r0 bottom value=N/A
U42 "AD8615AUJZ-REEL7" ADI-UJ-5_M 7070,3964 r180 bottom value=N/A
U43 "SN74LV541ATPWR" PW0020A_L 7350,2805 r0 bottom value=N/A
U44 "ALM2402FQPWPRQ1" FP-PWP0014H-MFG 7440,1105 r0 bottom value=N/A
U45 "AD8615AUJZ-REEL7" ADI-UJ-5_M 6950,1095 r0 bottom value=N/A
U46 "AD8615AUJZ-REEL7" ADI-UJ-5_M 7400,890 r270 bottom value=N/A
U47 "AD8615AUJZ-REEL7" ADI-UJ-5_M 7400,721.77 r270 bottom value=N/A
U48 "REF2033QDDCRQ1" FP-DDC0005A-MFG 7531.85,567.6 r0 bottom

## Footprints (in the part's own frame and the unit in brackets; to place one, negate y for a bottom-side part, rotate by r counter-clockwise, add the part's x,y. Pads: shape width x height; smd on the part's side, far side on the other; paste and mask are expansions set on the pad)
1755736 [mm] "THD, 2-Leads, Body 12.16x8.6mm, Pitch 5.08mm"
  rect 1.9x1.9 hole 1.4: 1(-2.54,0)
  round 1.9 hole 1.4: 2(2.54,0)
  silkscreen extent -6.08,-3.81 6.08,4.79, body extent -6.08,-3.8 6.16,4.87, height 12
1755778 [mm] "TERM BLOCK HDR 6POS VERT 5.08MM"
  round 2.4 hole 1.4: 1(-12.7,0) 2(-7.62,0) 3(-2.54,0) 4(2.54,0) 5(7.62,0) 6(12.7,0)
  silkscreen extent -16.24,-3.83 16.24,3.84, body extent -16.24,-3.84 16.24,4.76, height 12
7460307 [mm] "8 Pin Screw Terminal, Power Tap M4 Through Hole"
  round 2.21 hole 1.475: 1(-3.81,3.81) 2(-1.27,3.81) 3(1.27,3.81) 4(3.81,3.81) 5(3.81,-3.81) 6(1.27,-3.81) 7(-1.27,-3.81) 8(-3.81,-3.81)
  Top Layer keep-out region: -8.5,-8.5 8.5,-8.5 8.5,8.5 -8.5,8.5
  Bottom Layer keep-out region: -8.5,-8.5 8.5,-8.5 8.5,8.5 -8.5,8.5
  silkscreen extent -5.2,-5.2 5.2,5.2, body extent -4.5,-4.5 4.5,4.5, height 7
61200621621 [mm] "6 pins, straight, gold plating"
  rect 1.6x1.6 hole 1.1: 1(-2.54,-1.27)
  round 1.6 hole 1.1: 2(-2.54,1.27) 3(0,-1.27) 4(0,1.27) 5(2.54,-1.27) 6(2.54,1.27)
  silkscreen extent -7.74,-4.5 7.74,4.5, body extent -7.64,-4.43 7.64,4.75, height 9.13
ADI-UJ-5_M [mm] "SOT23, 5-Leads, Body 2.9x1.6mm, Pitch 0.95mm, IPC Low Density"
  rect 1.15x0.7 smd: 1(-1.225,0.95) 2(-1.225,0) 3(-1.225,-0.95) 4(1.225,-0.95) 5(1.225,0.95)
  silkscreen extent -1.35,-1.45 0.25,1.97, body extent -0.8,-1.45 0.8,1.45, height 1
C4AQQEW5650A3BJ [mm] "CAP FILM 65UF 5% 1.1KVDC RAD"
  round 4 hole 2: 1(-26.25,10.15) 2(-26.25,-10.15) 3(26.25,10.15) 4(26.25,-10.15)
  silkscreen extent -28.75,-22.5 28.75,22.5, body extent -29,-22.71 29.3,22.8, height 65.4
CONV_R-78E3.3-1.0 [mm]
  rect 1.508x1.508 hole 1: 1(-2.54,-2.25)
  round 1.508 hole 1: 2(0,-2.25) 3(2.54,-2.25)
  silkscreen extent -6.5,-4.25 5.75,4.25, body extent -5.8,-4.25 5.8,4.25, height 9.9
